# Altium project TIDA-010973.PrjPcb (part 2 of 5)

## Sheet TIDA-010973_SOM_PMIC.SchDoc
size 558 x 431 mm; Date: Not shown in title block; ApprovedBy: Not shown in title block; CheckedBy: Not shown in title block; Author: Not shown in title block; CompanyName: Not shown in title block; Engineer: Not shown in title block; Organization: Not shown in title block; Address1: Not shown in title block; Address2: Not shown in title block; Address3: Not shown in title block; Address4: Not shown in title block; DocumentNumber: 2; Revision: Use project parameter SCH_Rev; SheetNumber: 3; SheetTotal: 15; PageSetup: Record=PageOptions¦CenterHorizontal=True¦CenterVertical=True¦PrintScale=1.00¦XCorrection=1.00¦YCorrection=1.00¦PrintKind=0¦BorderSize=5000000¦LeftOffset=0¦BottomOffset=0¦Orientation=2¦PaperLength=1000¦PaperWidth=1000¦Scale=100¦PaperSource=15¦PrintQuality=600¦MediaType=1¦DitherType=10¦PaperKind=Letter¦PrintScaleMode=1
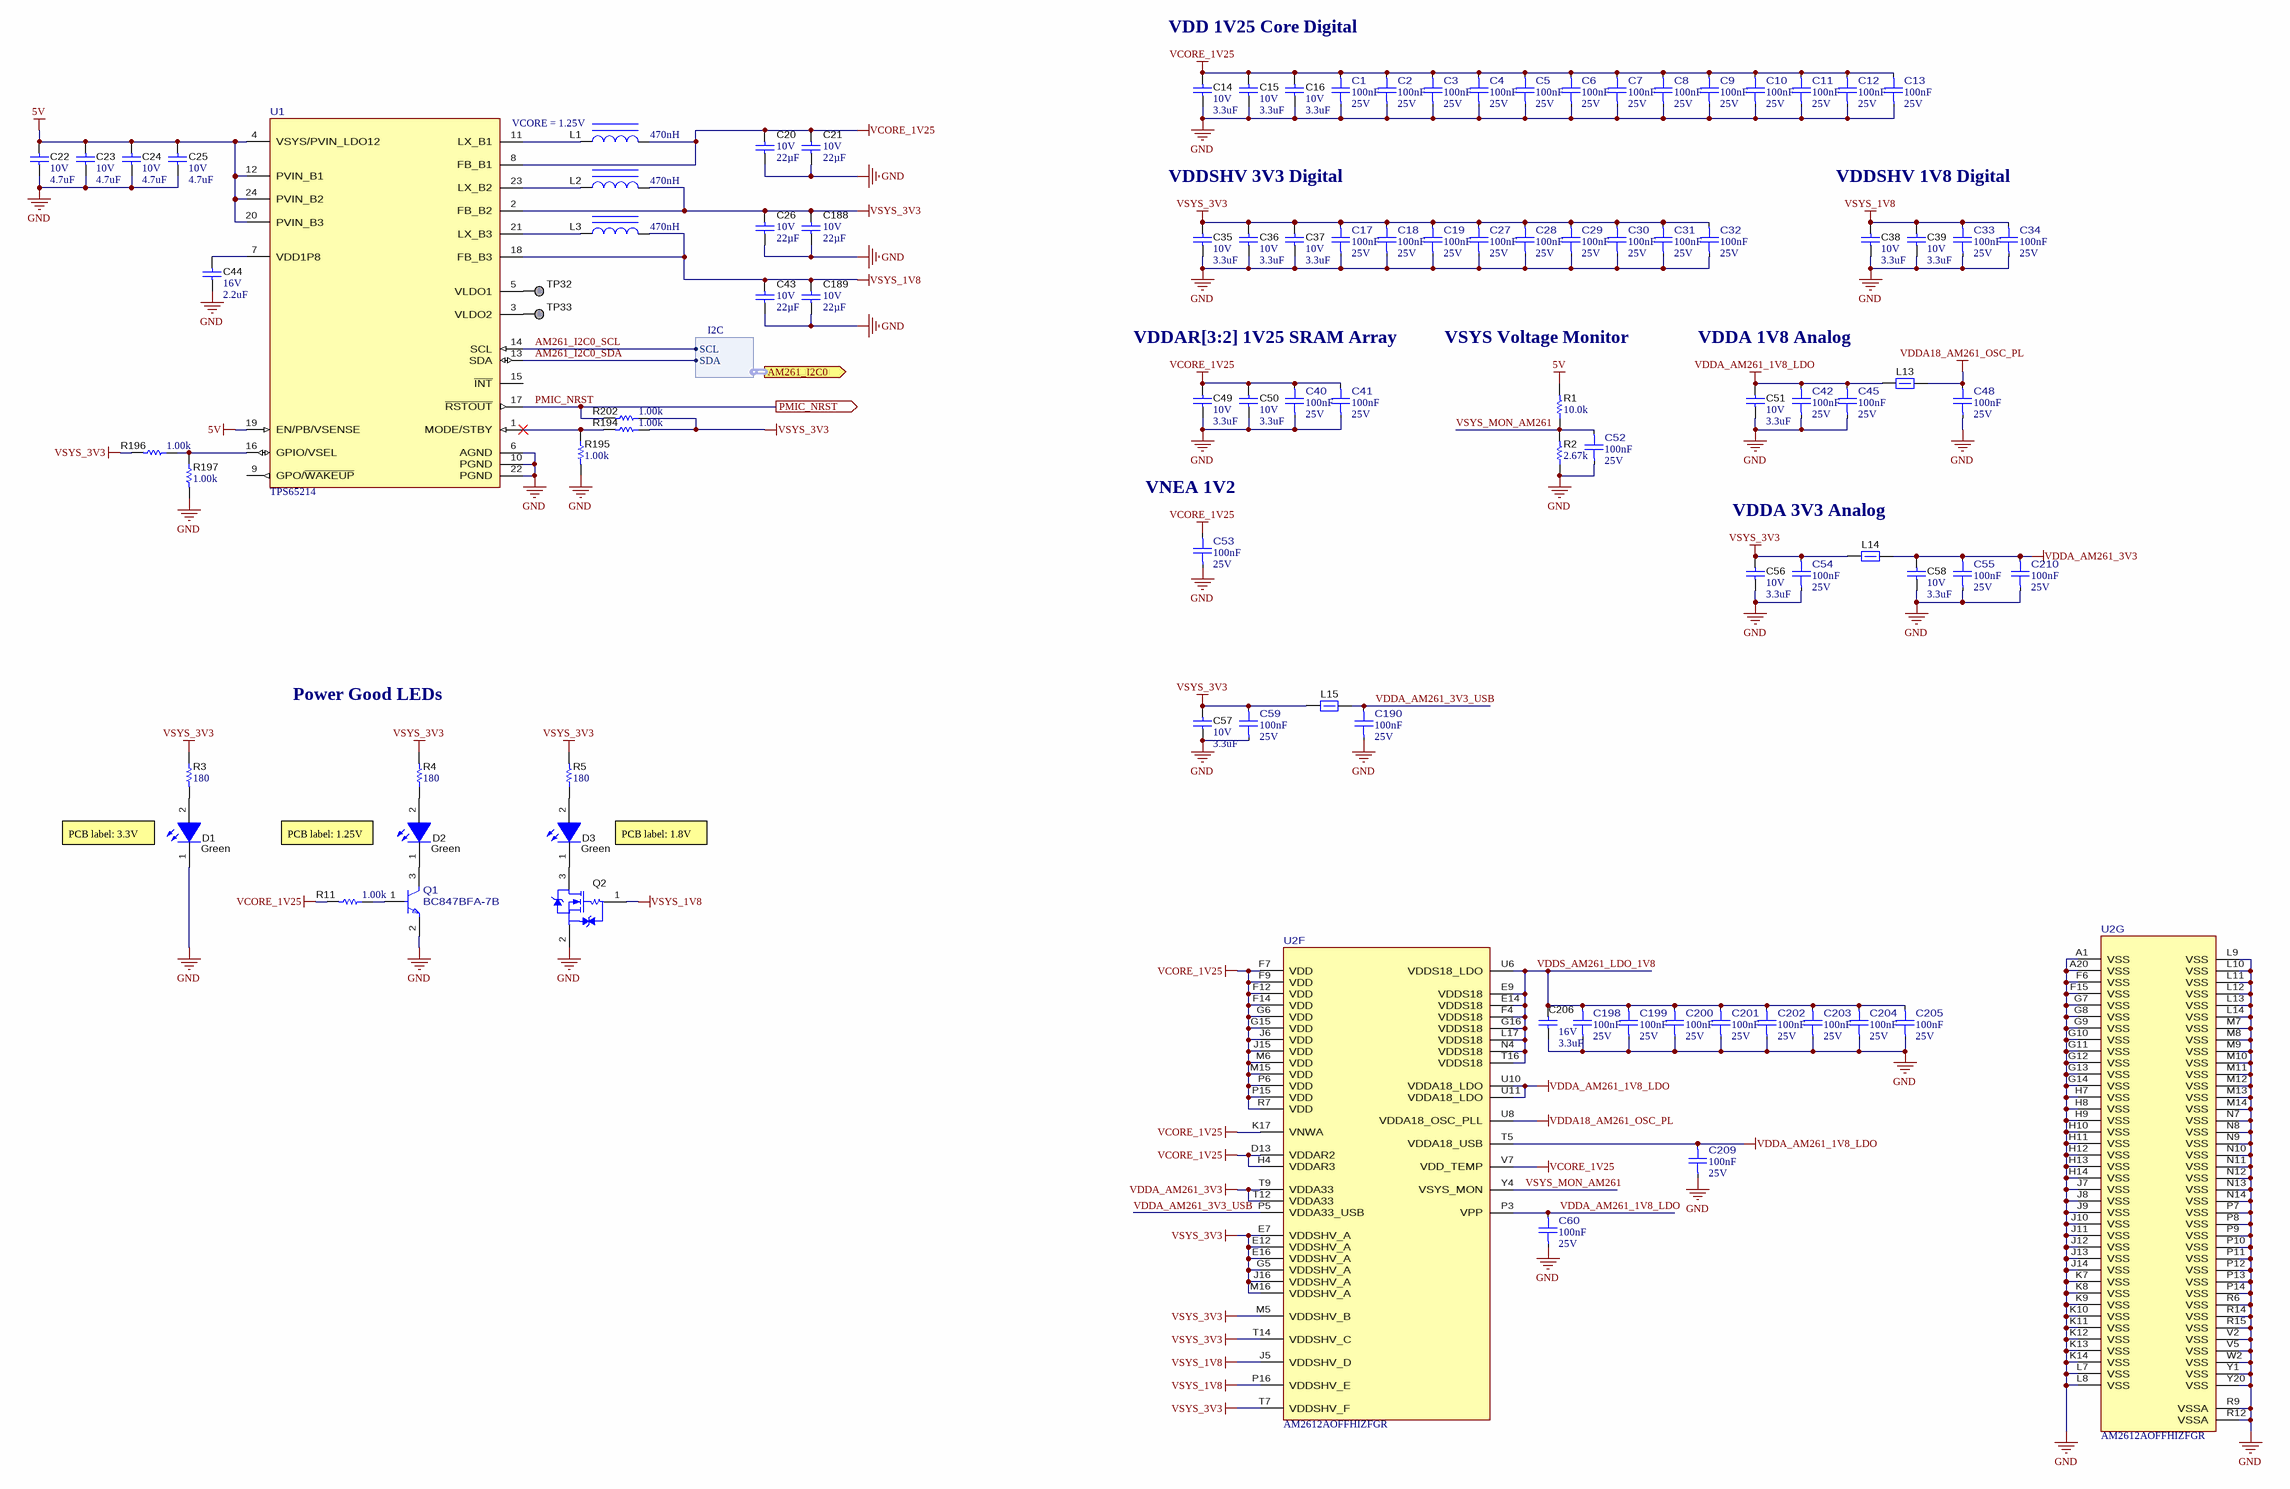
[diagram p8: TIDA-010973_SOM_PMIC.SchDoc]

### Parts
C1  ValueDisplayed: 100nF  VDC_V: 25V  [FP-885012104005_0201-IPC_C]  (hidden comment: 885012104005)
C2  ValueDisplayed: 100nF  VDC_V: 25V  [FP-885012104005_0201-IPC_C]  (hidden comment: 885012104005)
C3  ValueDisplayed: 100nF  VDC_V: 25V  [FP-885012104005_0201-IPC_C]  (hidden comment: 885012104005)
C4  ValueDisplayed: 100nF  VDC_V: 25V  [FP-885012104005_0201-IPC_C]  (hidden comment: 885012104005)
C5  ValueDisplayed: 100nF  VDC_V: 25V  [FP-885012104005_0201-IPC_C]  (hidden comment: 885012104005)
C6  ValueDisplayed: 100nF  VDC_V: 25V  [FP-885012104005_0201-IPC_C]  (hidden comment: 885012104005)
C7  ValueDisplayed: 100nF  VDC_V: 25V  [FP-885012104005_0201-IPC_C]  (hidden comment: 885012104005)
C8  ValueDisplayed: 100nF  VDC_V: 25V  [FP-885012104005_0201-IPC_C]  (hidden comment: 885012104005)
C9  ValueDisplayed: 100nF  VDC_V: 25V  [FP-885012104005_0201-IPC_C]  (hidden comment: 885012104005)
C10  ValueDisplayed: 100nF  VDC_V: 25V  [FP-885012104005_0201-IPC_C]  (hidden comment: 885012104005)
C11  ValueDisplayed: 100nF  VDC_V: 25V  [FP-885012104005_0201-IPC_C]  (hidden comment: 885012104005)
C12  ValueDisplayed: 100nF  VDC_V: 25V  [FP-885012104005_0201-IPC_C]  (hidden comment: 885012104005)
C13  ValueDisplayed: 100nF  VDC_V: 25V  [FP-885012104005_0201-IPC_C]  (hidden comment: 885012104005)
C14  VDC_V: 10V  ValueDisplayed: 3.3uF  [0402L]  (hidden comment: C1005X5R1A335K050BC)
C15  VDC_V: 10V  ValueDisplayed: 3.3uF  [0402L]  (hidden comment: C1005X5R1A335K050BC)
C16  VDC_V: 10V  ValueDisplayed: 3.3uF  [0402L]  (hidden comment: C1005X5R1A335K050BC)
C17  ValueDisplayed: 100nF  VDC_V: 25V  [FP-885012104005_0201-IPC_C]  (hidden comment: 885012104005)
C18  ValueDisplayed: 100nF  VDC_V: 25V  [FP-885012104005_0201-IPC_C]  (hidden comment: 885012104005)
C19  ValueDisplayed: 100nF  VDC_V: 25V  [FP-885012104005_0201-IPC_C]  (hidden comment: 885012104005)
C20  VDC_V: 10V  ValueDisplayed: 22µF  [0805_150]  (hidden comment: 885012107011)
C21  VDC_V: 10V  ValueDisplayed: 22µF  [0805_150]  (hidden comment: 885012107011)
C22  VDC_V: 10V  ValueDisplayed: 4.7uF  [0402_065S]  (hidden comment: C1005X5R1A475K050BC)
C23  VDC_V: 10V  ValueDisplayed: 4.7uF  [0402_065S]  (hidden comment: C1005X5R1A475K050BC)
C24  VDC_V: 10V  ValueDisplayed: 4.7uF  [0402_065S]  (hidden comment: C1005X5R1A475K050BC)
C25  VDC_V: 10V  ValueDisplayed: 4.7uF  [0402_065S]  (hidden comment: C1005X5R1A475K050BC)
C26  VDC_V: 10V  ValueDisplayed: 22µF  [0805_150]  (hidden comment: 885012107011)
C27  ValueDisplayed: 100nF  VDC_V: 25V  [FP-885012104005_0201-IPC_C]  (hidden comment: 885012104005)
C28  ValueDisplayed: 100nF  VDC_V: 25V  [FP-885012104005_0201-IPC_C]  (hidden comment: 885012104005)
C29  ValueDisplayed: 100nF  VDC_V: 25V  [FP-885012104005_0201-IPC_C]  (hidden comment: 885012104005)
C30  ValueDisplayed: 100nF  VDC_V: 25V  [FP-885012104005_0201-IPC_C]  (hidden comment: 885012104005)
C31  ValueDisplayed: 100nF  VDC_V: 25V  [FP-885012104005_0201-IPC_C]  (hidden comment: 885012104005)
C32  ValueDisplayed: 100nF  VDC_V: 25V  [FP-885012104005_0201-IPC_C]  (hidden comment: 885012104005)
C33  ValueDisplayed: 100nF  VDC_V: 25V  [FP-885012104005_0201-IPC_C]  (hidden comment: 885012104005)
C34  ValueDisplayed: 100nF  VDC_V: 25V  [FP-885012104005_0201-IPC_C]  (hidden comment: 885012104005)
C35  VDC_V: 10V  ValueDisplayed: 3.3uF  [0402L]  (hidden comment: C1005X5R1A335K050BC)
C36  VDC_V: 10V  ValueDisplayed: 3.3uF  [0402L]  (hidden comment: C1005X5R1A335K050BC)
C37  VDC_V: 10V  ValueDisplayed: 3.3uF  [0402L]  (hidden comment: C1005X5R1A335K050BC)
C38  VDC_V: 10V  ValueDisplayed: 3.3uF  [0402L]  (hidden comment: C1005X5R1A335K050BC)
C39  VDC_V: 10V  ValueDisplayed: 3.3uF  [0402L]  (hidden comment: C1005X5R1A335K050BC)
C40  ValueDisplayed: 100nF  VDC_V: 25V  [FP-885012104005_0201-MFG]  (hidden comment: 885012104005)
C41  ValueDisplayed: 100nF  VDC_V: 25V  [FP-885012104005_0201-MFG]  (hidden comment: 885012104005)
C42  ValueDisplayed: 100nF  VDC_V: 25V  [FP-885012104005_0201-IPC_C]  (hidden comment: 885012104005)
C43  VDC_V: 10V  ValueDisplayed: 22µF  [0805_150]  (hidden comment: 885012107011)
C44  VDC_V: 16V  ValueDisplayed: 2.2uF  [0603L]  (hidden comment: 885012106018)
C45  ValueDisplayed: 100nF  VDC_V: 25V  [FP-885012104005_0201-IPC_C]  (hidden comment: 885012104005)
C48  ValueDisplayed: 100nF  VDC_V: 25V  [FP-885012104005_0201-IPC_C]  (hidden comment: 885012104005)
C49  VDC_V: 10V  ValueDisplayed: 3.3uF  [0402L]  (hidden comment: C1005X5R1A335K050BC)
C50  VDC_V: 10V  ValueDisplayed: 3.3uF  [0402L]  (hidden comment: C1005X5R1A335K050BC)
C51  VDC_V: 10V  ValueDisplayed: 3.3uF  [0402L]  (hidden comment: C1005X5R1A335K050BC)
C52  ValueDisplayed: 100nF  VDC_V: 25V  [FP-885012104005_0201-IPC_C]  (hidden comment: 885012104005)
C53  ValueDisplayed: 100nF  VDC_V: 25V  [FP-885012104005_0201-IPC_C]  (hidden comment: 885012104005)
C54  ValueDisplayed: 100nF  VDC_V: 25V  [FP-885012104005_0201-IPC_C]  (hidden comment: 885012104005)
C55  ValueDisplayed: 100nF  VDC_V: 25V  [FP-885012104005_0201-IPC_C]  (hidden comment: 885012104005)
C56  VDC_V: 10V  ValueDisplayed: 3.3uF  [0402L]  (hidden comment: C1005X5R1A335K050BC)
C57  VDC_V: 10V  ValueDisplayed: 3.3uF  [0402L]  (hidden comment: C1005X5R1A335K050BC)
C58  VDC_V: 10V  ValueDisplayed: 3.3uF  [0402L]  (hidden comment: C1005X5R1A335K050BC)
C59  ValueDisplayed: 100nF  VDC_V: 25V  [FP-885012104005_0201-IPC_C]  (hidden comment: 885012104005)
C60  ValueDisplayed: 100nF  VDC_V: 25V  [FP-885012104005_0201-IPC_C]  (hidden comment: 885012104005)
C188  VDC_V: 10V  ValueDisplayed: 22µF  [0805_150]  (hidden comment: 885012107011)
C189  VDC_V: 10V  ValueDisplayed: 22µF  [0805_150]  (hidden comment: 885012107011)
C190  ValueDisplayed: 100nF  VDC_V: 25V  [FP-885012104005_0201-IPC_C]  (hidden comment: 885012104005)
C198  ValueDisplayed: 100nF  VDC_V: 25V  [FP-885012104005_0201-IPC_C]  (hidden comment: 885012104005)
C199  ValueDisplayed: 100nF  VDC_V: 25V  [FP-885012104005_0201-IPC_C]  (hidden comment: 885012104005)
C200  ValueDisplayed: 100nF  VDC_V: 25V  [FP-885012104005_0201-IPC_C]  (hidden comment: 885012104005)
C201  ValueDisplayed: 100nF  VDC_V: 25V  [FP-885012104005_0201-IPC_C]  (hidden comment: 885012104005)
C202  ValueDisplayed: 100nF  VDC_V: 25V  [FP-885012104005_0201-IPC_C]  (hidden comment: 885012104005)
C203  ValueDisplayed: 100nF  VDC_V: 25V  [FP-885012104005_0201-IPC_C]  (hidden comment: 885012104005)
C204  ValueDisplayed: 100nF  VDC_V: 25V  [FP-885012104005_0201-IPC_C]  (hidden comment: 885012104005)
C205  ValueDisplayed: 100nF  VDC_V: 25V  [FP-885012104005_0201-IPC_C]  (hidden comment: 885012104005)
C206  VDC_V: 16V  ValueDisplayed: 3.3uF  [0603L]  (hidden comment: C1608X6S1C335K080AC)
C209  ValueDisplayed: 100nF  VDC_V: 25V  [FP-885012104005_0201-IPC_C]  (hidden comment: 885012104005)
C210  ValueDisplayed: 100nF  VDC_V: 25V  [FP-885012104005_0201-IPC_C]  (hidden comment: 885012104005)
D1  value Green  [WL-SMCW_GREEN]  (hidden comment: 150060VS75000)
D2  value Green  [WL-SMCW_GREEN]  (hidden comment: 150060VS75000)
D3  value Green  [WL-SMCW_GREEN]  (hidden comment: 150060VS75000)
L1  ValueDisplayed: 470nH  [WE-PMCI_0603LP]  (hidden comment: 74479262147)
L2  ValueDisplayed: 470nH  [WE-PMCI_0603LP]  (hidden comment: 74479262147)
L3  ValueDisplayed: 470nH  [WE-PMCI_0603LP]  (hidden comment: 74479262147)
L13  74279271  [0402L]  (value not drawn)
L14  74279271  [0402L]  (value not drawn)
L15  74279271  [0402L]  (value not drawn)
Q1  BC847BFA-7B  [FP-BC847BFA-7B_DFN3-MFG]
Q2  CSD13383F4  [YJC0003A]  (value not drawn)
R1  ValueDisplayed: 10.0k  [0402L]  (hidden comment: CRCW040210K0FKED)
R2  ValueDisplayed: 2.67k  [0402L]  (hidden comment: CRCW04022K67FKED)
R3  ValueDisplayed: 180  [0402L]  (hidden comment: CRCW0402180RJNED)
R4  ValueDisplayed: 180  [0402L]  (hidden comment: CRCW0402180RJNED)
R5  ValueDisplayed: 180  [0402L]  (hidden comment: CRCW0402180RJNED)
R11  ValueDisplayed: 1.00k  [0402L]  (hidden comment: CRCW04021K00FKED)
R194  ValueDisplayed: 1.00k  [0402L]  (hidden comment: CRCW04021K00FKED)
R195  ValueDisplayed: 1.00k  [0402L]  (hidden comment: CRCW04021K00FKED)
R196  ValueDisplayed: 1.00k  [0402L]  (hidden comment: CRCW04021K00FKED)
R197  ValueDisplayed: 1.00k  [0402L]  (hidden comment: CRCW04021K00FKED)
R202  ValueDisplayed: 1.00k  [0402L]  (hidden comment: CRCW04021K00FKED)
TP32  TESTPOINT  [TP_25MIL-SMT]  (value not drawn)  (no BOM)
TP33  TESTPOINT  [TP_25MIL-SMT]  (value not drawn)  (no BOM)
U1  TPS65214  [VAF0024A-MFG]
U2  AM2612AOFFHIZFGR  [ZFG0304A-MFG]  (parts F,G of 7)

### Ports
AM261_I2C0 (out, harness I2C), PMIC_NRST (out)

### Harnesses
I2C: SCL, SDA

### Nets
5V: C22.1 C23.1 C24.1 C25.1 R1.2 U1.4(VSYS/PVIN_LDO12) U1.12(PVIN_B1) U1.19(EN/PB/VSENSE) U1.20(PVIN_B3) U1.24(PVIN_B2)
GND: C1.1 C2.1 C3.1 C4.1 C5.1 C6.1 C7.1 C8.1 C9.1 C10.1 C11.1 C12.1 C13.1 C14.2 C15.2 C16.2 C17.1 C18.1 C19.1 C20.2 C21.2 C22.2 C23.2 C24.2 C25.2 C26.2 C27.1 C28.1 C29.1 C30.1 C31.1 C32.1 C33.1 C34.1 C35.2 C36.2 C37.2 C38.2 C39.2 C40.1 C41.1 C42.1 C43.2 C44.2 C45.1 C48.1 C49.2 C50.2 C51.2 C52.1 C53.1 C54.1 C55.1 C56.2 C57.2 C58.2 C59.1 C60.1 C188.2 C189.2 C190.1 C198.1 C199.1 C200.1 C201.1 C202.1 C203.1 C204.1 C205.1 C206.2 C209.2 C210.1 D1.1(K) Q1.2(E) Q2.2(S) R2.1 R195.2 R197.2 U1.6(AGND) U1.10(PGND) U1.22(PGND) U2.A1(VSS) U2.A20(VSS) U2.F6(VSS) U2.F15(VSS) U2.G7(VSS) U2.G8(VSS) U2.G9(VSS) U2.G10(VSS) U2.G11(VSS) U2.G12(VSS) U2.G13(VSS) U2.G14(VSS) U2.H7(VSS) U2.H8(VSS) U2.H9(VSS) U2.H10(VSS) U2.H11(VSS) U2.H12(VSS) U2.H13(VSS) U2.H14(VSS) U2.J7(VSS) U2.J8(VSS) U2.J9(VSS) U2.J10(VSS) U2.J11(VSS) U2.J12(VSS) U2.J13(VSS) U2.J14(VSS) U2.K7(VSS) U2.K8(VSS) U2.K9(VSS) U2.K10(VSS) U2.K11(VSS) U2.K12(VSS) U2.K13(VSS) U2.K14(VSS) U2.L7(VSS) U2.L8(VSS) U2.L9(VSS) U2.L10(VSS) U2.L11(VSS) U2.L12(VSS) U2.L13(VSS) U2.L14(VSS) U2.M7(VSS) U2.M8(VSS) U2.M9(VSS) U2.M10(VSS) U2.M11(VSS) U2.M12(VSS) U2.M13(VSS) U2.M14(VSS) U2.N7(VSS) U2.N8(VSS) U2.N9(VSS) U2.N10(VSS) U2.N11(VSS) U2.N12(VSS) U2.N13(VSS) U2.N14(VSS) U2.P7(VSS) U2.P8(VSS) U2.P9(VSS) U2.P10(VSS) U2.P11(VSS) U2.P12(VSS) U2.P13(VSS) U2.P14(VSS) U2.R6(VSS) U2.R9(VSSA) U2.R12(VSSA) U2.R14(VSS) U2.R15(VSS) U2.V2(VSS) U2.V5(VSS) U2.W2(VSS) U2.Y1(VSS) U2.Y20(VSS)
VCORE_1V25: C1.2 C2.2 C3.2 C4.2 C5.2 C6.2 C7.2 C8.2 C9.2 C10.2 C11.2 C12.2 C13.2 C14.1 C15.1 C16.1 C20.1 C21.1 C40.2 C41.2 C49.1 C50.1 C53.2 L1.2 R11.2 U1.8(FB_B1) U2.D13(VDDAR2) U2.F7(VDD) U2.F9(VDD) U2.F12(VDD) U2.F14(VDD) U2.G6(VDD) U2.G15(VDD) U2.H4(VDDAR3) U2.J6(VDD) U2.J15(VDD) U2.K17(VNWA) U2.M6(VDD) U2.M15(VDD) U2.P6(VDD) U2.P15(VDD) U2.R7(VDD) U2.V7(VDD_TEMP)
VDDA18_AM261_OSC_PL: C48.2 L13.2 U2.U8(VDDA18_OSC_PLL)
VDDA_AM261_1V8_LDO: C42.2 C45.2 C51.1 C60.2 C209.1 L13.1 U2.P3(VPP) U2.T5(VDDA18_USB) U2.U10(VDDA18_LDO) U2.U11(VDDA18_LDO)
VDDA_AM261_3V3: C55.2 C58.1 C210.2 L14.2 U2.T9(VDDA33) U2.T12(VDDA33)
VSYS_1V8: C33.2 C34.2 C38.1 C39.1 C43.1 C189.1 L3.2 Q2.1(G) U1.18(FB_B3) U2.J5(VDDSHV_D) U2.P16(VDDSHV_E)
VSYS_3V3: C17.2 C18.2 C19.2 C26.1 C27.2 C28.2 C29.2 C30.2 C31.2 C32.2 C35.1 C36.1 C37.1 C54.2 C56.1 C57.1 C59.2 C188.1 L2.2 L14.1 L15.1 R3.1 R4.2 R5.2 R194.1 R196.2 R202.1 U1.2(FB_B2) U2.E7(VDDSHV_A) U2.E12(VDDSHV_A) U2.E16(VDDSHV_A) U2.G5(VDDSHV_A) U2.J16(VDDSHV_A) U2.M5(VDDSHV_B) U2.M16(VDDSHV_A) U2.T7(VDDSHV_F) U2.T14(VDDSHV_C)
AM261_I2C0_SCL: U1.14(SCL) ; port AM261_I2C0.SCL  [project net AM261_I2C0.SCL]
AM261_I2C0_SDA: U1.13(SDA) ; port AM261_I2C0.SDA  [project net AM261_I2C0.SDA]
PMIC_NRST: R202.2 U1.17(~{RSTOUT}) ; port PMIC_NRST
VDDA_AM261_3V3_USB: C190.2 L15.2 U2.P5(VDDA33_USB)
VDDS_AM261_LDO_1V8: C198.2 C199.2 C200.2 C201.2 C202.2 C203.2 C204.2 C205.2 C206.1 U2.E9(VDDS18) U2.E14(VDDS18) U2.F4(VDDS18) U2.G16(VDDS18) U2.L17(VDDS18) U2.N4(VDDS18) U2.T16(VDDS18) U2.U6(VDDS18_LDO)
VSYS_MON_AM261: C52.2 R1.1 R2.2 U2.Y4(VSYS_MON)
NetC44_1: C44.1 U1.7(VDD1P8)
NetD1_2: D1.2(A) R3.2
NetD2_1: D2.1(K) Q1.3(C)
NetD2_2: D2.2(A) R4.1
NetD3_1: D3.1(K) Q2.3(D)
NetD3_2: D3.2(A) R5.1
NetL1_1: L1.1 U1.11(LX_B1)
NetL2_1: L2.1 U1.23(LX_B2)
NetL3_1: L3.1 U1.21(LX_B3)
NetQ1_1: Q1.1(B) R11.1
NetR194_2: R194.2 R195.1 U1.1(MODE/STBY)
NetR196_1: R196.1 R197.1 U1.16(GPIO/VSEL)
NetTP32_1: TP32.1 U1.5(VLDO1)
NetTP33_1: TP33.1 U1.3(VLDO2)

Not connected (* = marked no-connect by the designer): U1 9(GPO/~{WAKEUP}) 15(~{INT})

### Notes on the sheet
- VDD 1V25 Core Digital
- VCORE = 1.25V
- VDDSHV 3V3 Digital
- VDDSHV 1V8 Digital
- VDDAR[3:2] 1V25 SRAM Array
- VSYS Voltage Monitor
- VDDA 1V8 Analog
- (near C53) VNEA 1V2
- VDDA 3V3 Analog
- Power Good LEDs
- PCB label: 3.3V
- PCB label: 1.25V
- PCB label: 1.8V

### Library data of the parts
C1-C13 C17-C19 C27-C34 C40-C42 C45 C48 C52-C55 C59 C60 C190 C198-C205 C209 C210 = CMP-0049180-1: 0.1 µF ±10% 25V Ceramic Capacitor X5R 0201 (0603 Metric); Manufacturer: Wurth Electronics; AEC Qualified: No; SizeZ_mm: 0.33mm; TempCo: 15%; Value: 100nF
C14-C16 C35-C39 C49-C51 C56-C58 = CMP-0006265-2: CAP, CERM, 3.3 uF, 10 V, +/- 10%, X5R, 0402; Manufacturer: TDK; TaMin_C: -55°C; ESR_ohm: 4.157m; Polarized: N; SizeAreaWB_mm2: 3; Value1: 0.004157 ohm; U/M: EA; Value: 3.3uF; TaMax_C: 85°C; SizeZ_mm: 0.6; SizeX_mm: 1; SizeY_mm: 0.5; Cap_Case: 0402; Cap_F: 3.3µF; IRMS_A: 2.45391A; AEC Category: Q200
C20 C21 C26 C43 C188 C189 = CMP-0078153-1: CAP, CERM, 22 µF, 10 V,+/- 20%, X5R, 0805; Manufacturer: Wurth Elektronik; TaMin_C: -55°C; Polarized: N; SizeAreaWB_mm2: 6.75; U/M: EA; Value: 22uF; TaMax_C: 85°C; SizeZ_mm: 1.5; SizeX_mm: 2; SizeY_mm: 1.25; Cap_Case: 0805; SizeArea_mm2: 2.5; AEC Category: Q200
C22-C25 = CMP-0006268-2: CAP, CERM, 4.7 uF, 10 V, +/- 10%, X5R, 0402; Manufacturer: TDK; TaMin_C: -55°C; ESR_ohm: 3.417m; Polarized: N; SizeAreaWB_mm2: 3; Value1: 0.003417 ohm; U/M: EA; Value: 4.7uF; TaMax_C: 85°C; SizeZ_mm: 0.65; SizeX_mm: 1; SizeY_mm: 0.5; Cap_Case: 0402_065; Cap_F: 4.7µF; IRMS_A: 2.7063A; AEC Category: Q200
C44 = CMP-0006825-5: CAP, CERM, 2.2 uF, 16 V, +/- 20%, X5R, 0603; Manufacturer: Wurth Elektronik; TaMin_C: -55°C; Polarized: N; SizeAreaWB_mm2: 4.68; Value1: Unknown; U/M: EA; Value: 2.2uF; TaMax_C: 85°C; SizeZ_mm: 1; SizeX_mm: 1.6; SizeY_mm: 0.8; Cap_Case: 0603; SizeArea_mm2: 1.28; Cap_F: 2.2µF; AEC Category: Q200
C206 = CMP-0007027-4: CAP, CERM, 3.3 uF, 16 V, +/- 10%, X6S, 0603; Manufacturer: TDK; TaMin_C: -55°C; ESR_ohm: 4.796m; Polarized: N; SizeAreaWB_mm2: 4.68; Value1: 0.004796 ohm; U/M: EA; Value: 3.3uF; TaMax_C: 105°C; SizeZ_mm: 1; SizeX_mm: 1.6; SizeY_mm: 0.8; Cap_Case: 0603; SizeArea_mm2: 1.28; Cap_F: 3.3µF; IRMS_A: 2.37519A; AEC Category: Q200
D1-D3 = CMP-0002894-2: LED, Green, SMD; Manufacturer: Wurth Elektronik; Type: AlInGaP; Value2: 2V; Io_A: 20mA; Value1: W
L1-L3 = CMP-0064306-1: Inductor, Shielded, 470 nH, 1.5 A, 0.1 ohm, SMD; Manufacturer: Wurth Elektronik; Isat: 2.5A @ 30% inductance drop; Irms: 1.5A @ 40C rise; Green_Lifecycle: Active; SizeAreaWB_mm2: 4.68; DCR_ohm: 1d; Green_REACh: Passed; Value1: 0.1 ohm; Value: 470nH; Imax_A: 1.5A; SizeZ_mm: 0.8; SizeX_mm: 1.6; SizeArea_mm2: 1.28; AEC Qualified: N; AEC Category: Q200
L13-L15 = CMP-0003214-1: Ferrite Bead, 120 ohm @ 100 MHz, 0.5 A, 0402; Manufacturer: Wurth Elektronik; Ztyp@1GHz_Ohm: 175.42; ZTyp@100MHz_Ohm: 120; SizeAreaWB_mm2: 3; DCR_ohm: 2d; Value1: 0.2 ohm; Value: 120 ohm; Imax_A: 5dA; SizeZ_mm: 0.6; SizeX_mm: 1; SizeY_mm: 0.5; Value2: 0.5A
Q1 = CMP-0090098-1: 100mA 45V NPN Signal Transistor DFN0806; Manufacturer: Diodes Inc.; Unity Gain Freq: 170MHz; Collector Base Voltage: 50V; Power_W: 435mW; AEC Qualified: Yes; Hfe Testic: 2mA; Number Of Npn: 1; Hfe Testvce: 5V; TJmax_C: +150°C; HfeMax: 470; Vceo_V: 150V; SizeZ_mm: 0.4mm; Emitter Base Voltage: 6V; Vcesat1_V: 122mV; Standoff Height: 0mm; Hfe Min: 200; AEC Grade: Grade 0; Rthja Max: 287°C/W
Q2 = CMP-0000198-1: MOSFET, N-CH, 12 V, 2.9 A, YJC0003A (PICOSTAR-3); Alternate Manufacturer: None; Manufacturer: Texas Instruments; SizeZ_mm: 0.35; ChType: N; Value2: 2 nC; Value1: 0.04; VdsMax_V: 12V; SizeX_mm: 1.035; SizeY_mm: 0.635; Vgs_V: 10V; Value: 12V; Rdson45_ohm: 0.044; SizeArea_mm2: 0.657225; AEC Category: Q101; IdsMax_A: 2.9A; SizeAreaWB_mm2: 3.327225; U/M: EA; QgTyp_nC: 2
R1 = CMP-0025958-3: RES, 10.0 k, 1%, 0.063 W, AEC-Q200 Grade 0, 0402; Manufacturer: Vishay-Dale; Power_W: 63mW; TempCo: 100 ppm/C; Value_Code: 10k0; Value: 10.0k; EIA_Code: E96; Res_ohm: 10k; SizeX_mm: 1; SizeY_mm: 0.5; SizeZ_mm: 0.6; Value2: 0.063W; AEC Qualified: Y; VDC_V: 50V; AEC Category: Q200; AEC Grade: 0
R2 = CMP-0026240-2: RES, 2.67 k, 1%, 0.063 W, AEC-Q200 Grade 0, 0402; Manufacturer: Vishay-Dale; Power_W: 63mW; TempCo: 100 ppm/C; Value_Code: 2k67; Value: 2.67k; EIA_Code: E96; SizeX_mm: 1; SizeY_mm: 0.5; SizeZ_mm: 0.6; Value2: 0.063W; AEC Qualified: Y; VDC_V: 50V; AEC Category: Q200; AEC Grade: 0
R3-R5 = CMP-0026849-3: RES, 180, 5%, 0.063 W, AEC-Q200 Grade 0, 0402; Manufacturer: Vishay-Dale; Power_W: 63mW; TempCo: 200 ppm/C; Value_Code: 180R; Value: 180; EIA_Code: E24; SizeX_mm: 1; SizeY_mm: 0.5; SizeZ_mm: 0.6; Value2: 0.063W; AEC Qualified: Y; VDC_V: 50V; AEC Category: Q200; AEC Grade: 0
R11 R194-R197 R202 = CMP-0026071-3: RES, 1.00 k, 1%, 0.063 W, AEC-Q200 Grade 0, 0402; Manufacturer: Vishay-Dale; Power_W: 63mW; TempCo: 100 ppm/C; Value_Code: 1k00; Value: 1.00k; EIA_Code: E96; Res_ohm: 1k; SizeX_mm: 1; SizeY_mm: 0.5; SizeZ_mm: 0.6; Value2: 0.063W; AEC Qualified: Y; VDC_V: 50V; AEC Category: Q200; AEC Grade: 0
TP32 TP33 = CMP-0078143-4: TEST POINT.  No entry in BOM.
U1 = CMP-0121651-1: Integrated Power Management IC for ARM Cortex®—Low Power Processors and FPGAs; Manufacturer: Texas Instruments; SizeZ_mm: 0.8mm; AEC Qualified: No; Max Supply Voltage: 5.5V; Min Supply Voltage: 2.5V; Number Of Outputs: 5; Output Voltage: 0.6-3.4/0.6-3.4/0.6-3.3/0.6-3.3V; Standoff Height: 0mm; TaMax_C: +105°C; TaMin_C: -40°C; TJmax_C: +125°C
U2 = CMP-0126016-1: ARM® Cortex®-R5F Sitara™ Microcontroller IC 32-Bit Dual-Core 500MHz 512KB (512K x 8) Tightly Coupled Memory (TCM) 304-NFBGA (13.25x13.25); Manufacturer: Texas Instruments; SizeZ_mm: 1.3mm; AEC Qualified: No; Core Architecture: ARM Cortex-R5F; Data Bus Width: 32bits; Interface: I2C,SPI,UART,CAN,USB,LIN,Ethernet; Max Supply Voltage: 3.465V; Min Supply Voltage: 1.14V; Number Of A/D Converters: 3; Number Of Adc Channels: 7; Number Of Cores: 2; Number Of Ethernet Channels: 1; Number Of I/Os: 141; Number Of Pwm Channels: 10; Number Of Spi Channels: 4; Number Of Uart Channels: 6; Ram Size: 1.5MBytes; Standoff Height: 0.23mm; TJmax_C: +125°C

## Sheet TIDA-010973_SOM_MCU.SchDoc
size 558 x 431 mm; Date: Not shown in title block; ApprovedBy: Not shown in title block; CheckedBy: Not shown in title block; Author: Not shown in title block; CompanyName: Not shown in title block; Engineer: Not shown in title block; Organization: Not shown in title block; Address1: Not shown in title block; Address2: Not shown in title block; Address3: Not shown in title block; Address4: Not shown in title block; DocumentNumber: 2; Revision: Use project parameter SCH_Rev; SheetNumber: 4; SheetTotal: 15; PageSetup: Record=PageOptions¦CenterHorizontal=True¦CenterVertical=True¦PrintScale=1.00¦XCorrection=1.00¦YCorrection=1.00¦PrintKind=0¦BorderSize=5000000¦LeftOffset=0¦BottomOffset=0¦Orientation=2¦PaperLength=1000¦PaperWidth=1000¦Scale=100¦PaperSource=15¦PrintQuality=600¦MediaType=1¦DitherType=10¦PaperKind=Letter¦PrintScaleMode=1
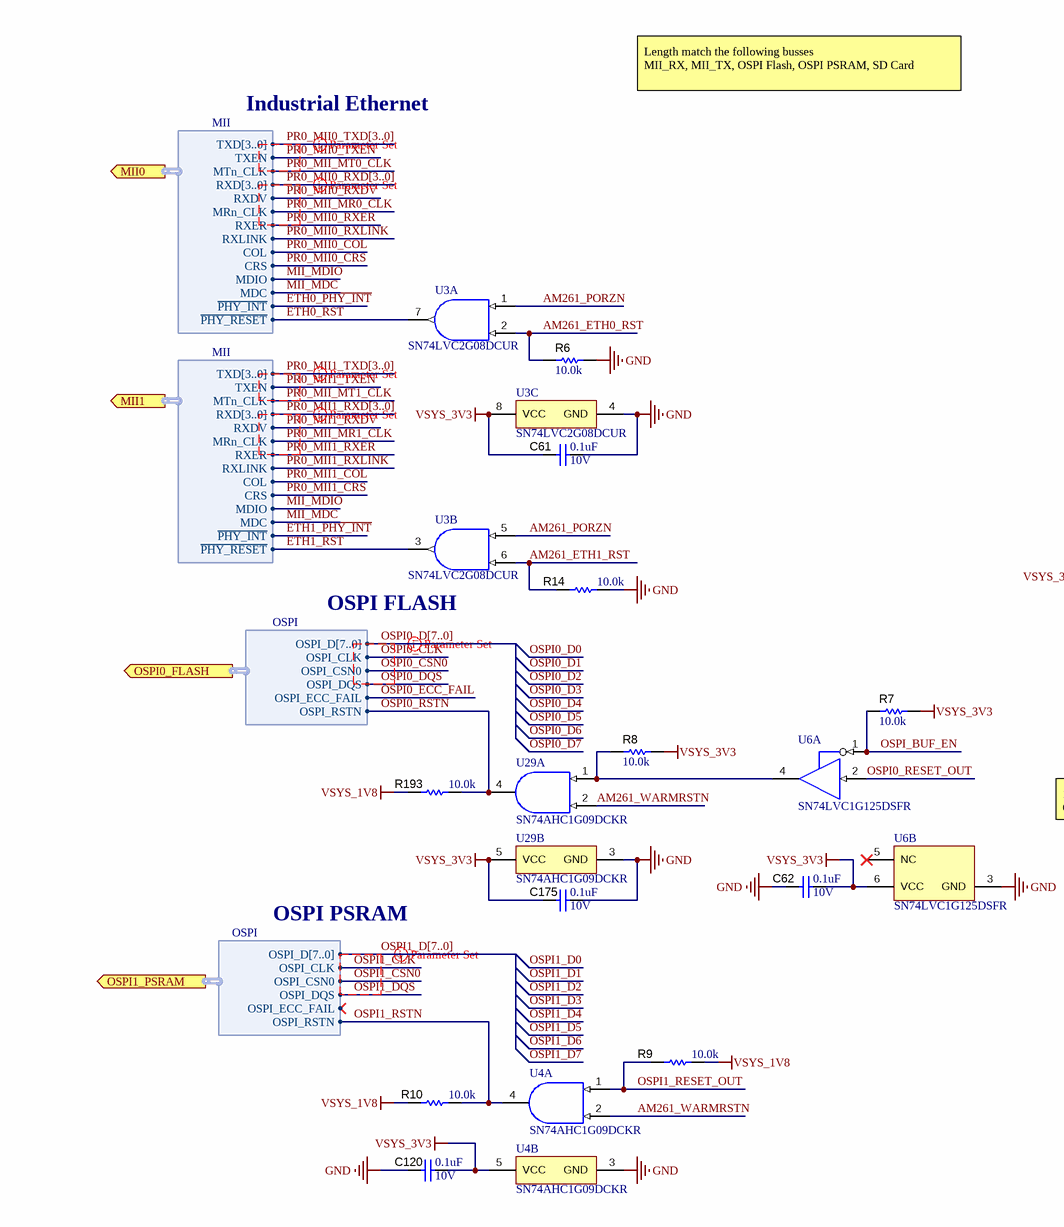
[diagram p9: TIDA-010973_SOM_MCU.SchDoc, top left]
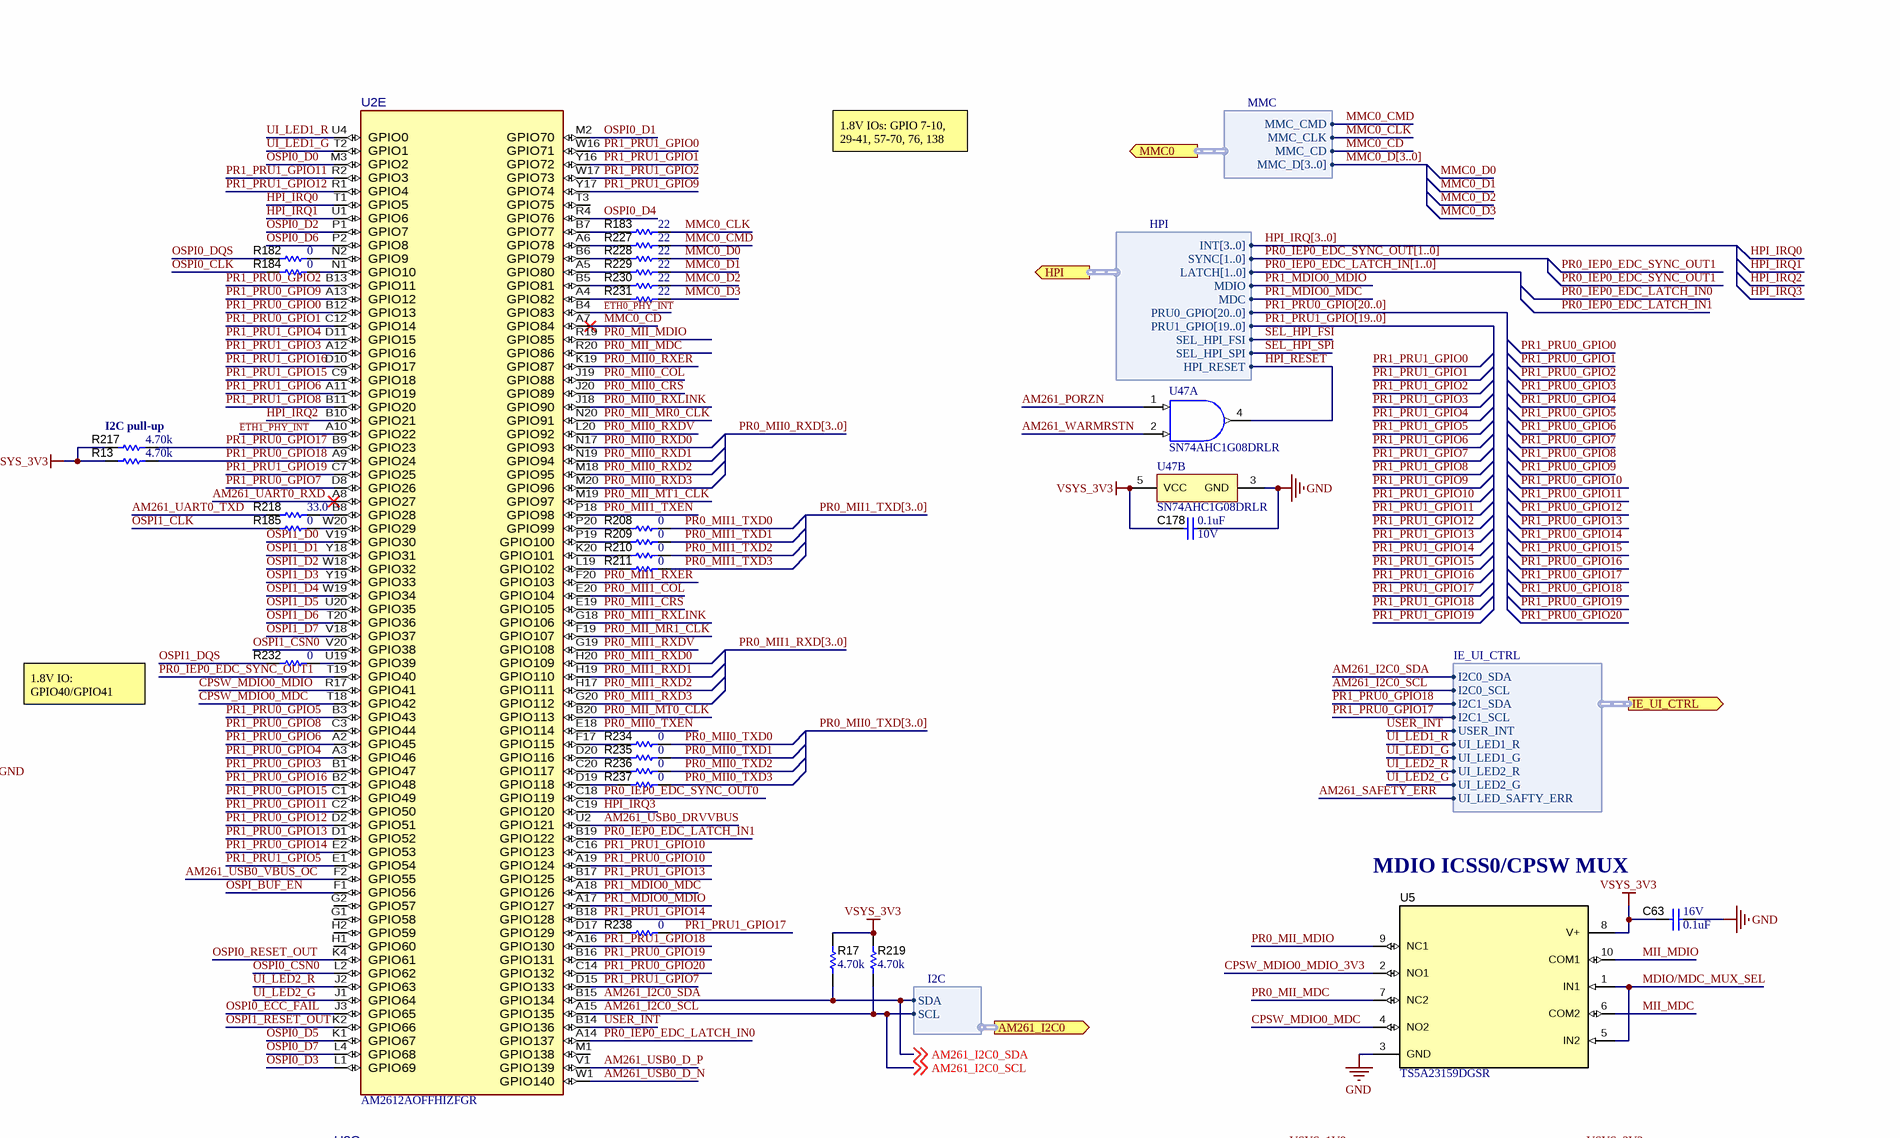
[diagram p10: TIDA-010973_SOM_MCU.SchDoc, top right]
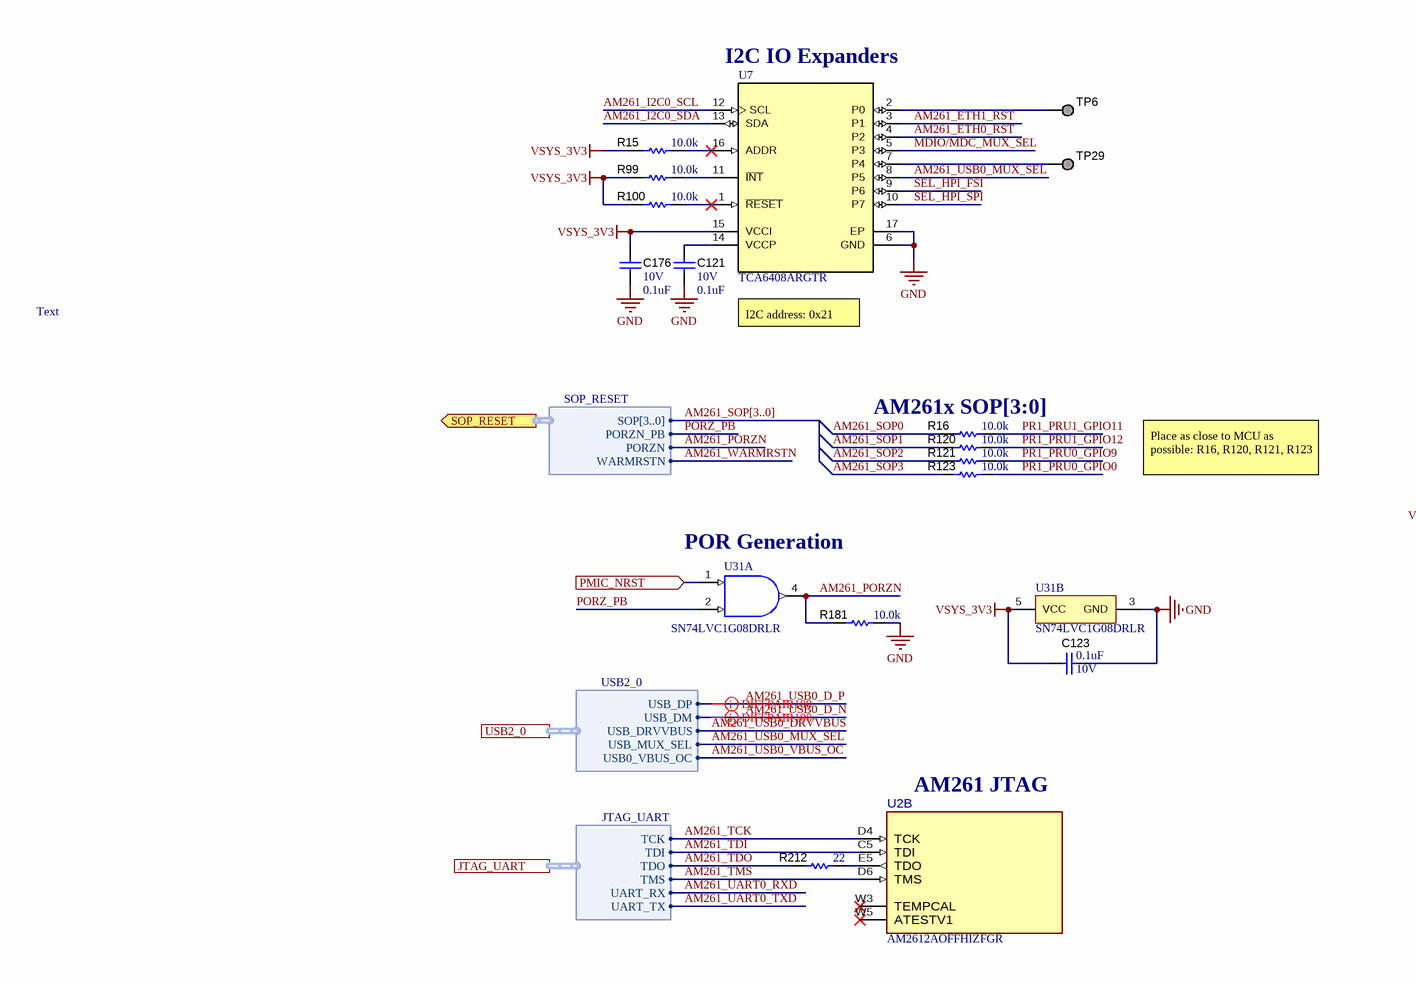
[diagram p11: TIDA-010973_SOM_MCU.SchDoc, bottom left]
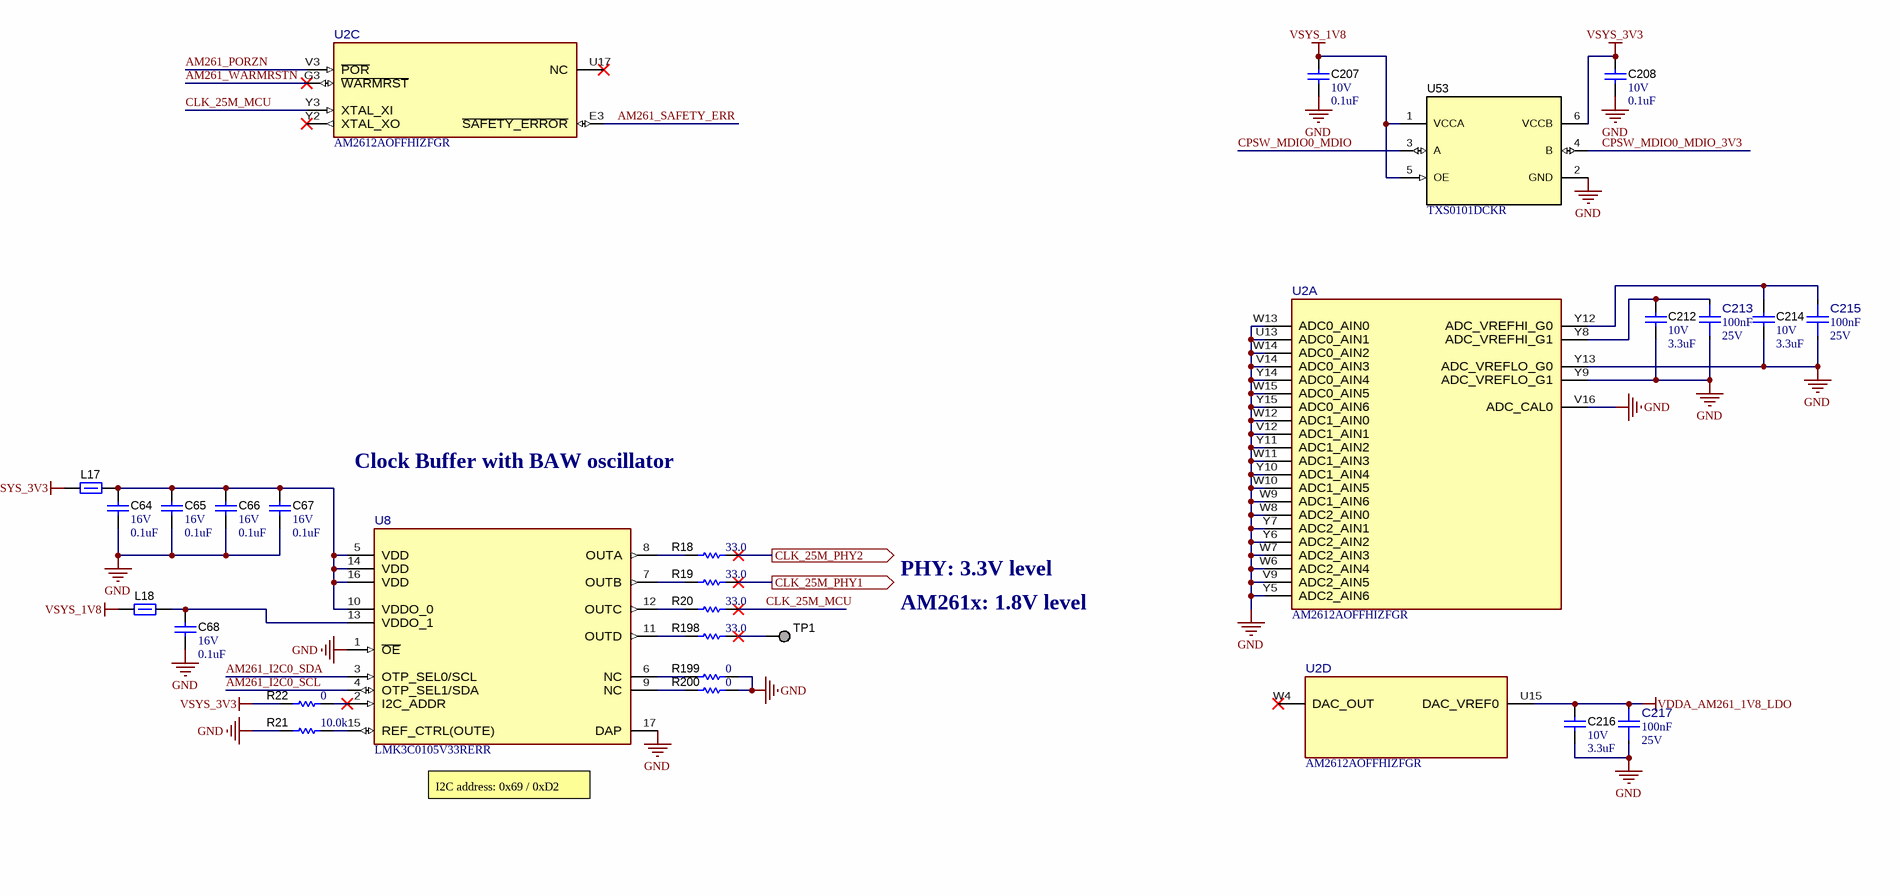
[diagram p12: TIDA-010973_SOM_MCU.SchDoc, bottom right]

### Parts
C61  VDC_V: 10V  ValueDisplayed: 0.1uF  [0402L]  (hidden comment: 885012105010)
C62  VDC_V: 10V  ValueDisplayed: 0.1uF  [0402L]  (hidden comment: 885012105010)
C63  VDC_V: 16V  ValueDisplayed: 0.1uF  [0402L]  (hidden comment: 885012205037)
C64  VDC_V: 16V  ValueDisplayed: 0.1uF  [0402L]  (hidden comment: 885012205037)
C65  VDC_V: 16V  ValueDisplayed: 0.1uF  [0402L]  (hidden comment: 885012205037)
C66  VDC_V: 16V  ValueDisplayed: 0.1uF  [0402L]  (hidden comment: 885012205037)
C67  VDC_V: 16V  ValueDisplayed: 0.1uF  [0402L]  (hidden comment: 885012205037)
C68  VDC_V: 16V  ValueDisplayed: 0.1uF  [0402L]  (hidden comment: 885012205037)
C120  VDC_V: 10V  ValueDisplayed: 0.1uF  [0402L]  (hidden comment: 885012105010)
C121  VDC_V: 10V  ValueDisplayed: 0.1uF  [0402L]  (hidden comment: 885012105010)
C123  VDC_V: 10V  ValueDisplayed: 0.1uF  [0402L]  (hidden comment: 885012105010)
C175  VDC_V: 10V  ValueDisplayed: 0.1uF  [0402L]  (hidden comment: 885012105010)
C176  VDC_V: 10V  ValueDisplayed: 0.1uF  [0402L]  (hidden comment: 885012105010)
C178  VDC_V: 10V  ValueDisplayed: 0.1uF  [0402L]  (hidden comment: 885012105010)
C207  VDC_V: 10V  ValueDisplayed: 0.1uF  [0402L]  (hidden comment: 885012105010)
C208  VDC_V: 10V  ValueDisplayed: 0.1uF  [0402L]  (hidden comment: 885012105010)
C212  VDC_V: 10V  ValueDisplayed: 3.3uF  [0402L]  (hidden comment: C1005X5R1A335K050BC)
C213  ValueDisplayed: 100nF  VDC_V: 25V  [FP-885012104005_0201-IPC_C]  (hidden comment: 885012104005)
C214  VDC_V: 10V  ValueDisplayed: 3.3uF  [0402L]  (hidden comment: C1005X5R1A335K050BC)
C215  ValueDisplayed: 100nF  VDC_V: 25V  [FP-885012104005_0201-IPC_C]  (hidden comment: 885012104005)
C216  VDC_V: 10V  ValueDisplayed: 3.3uF  [0402L]  (hidden comment: C1005X5R1A335K050BC)
C217  ValueDisplayed: 100nF  VDC_V: 25V  [FP-885012104005_0201-IPC_C]  (hidden comment: 885012104005)
L17  742792604  [0603L]  (value not drawn)
L18  742792604  [0603L]  (value not drawn)
R6  ValueDisplayed: 10.0k  [0402L]  (hidden comment: CRCW040210K0FKED)
R7  ValueDisplayed: 10.0k  [0402L]  (hidden comment: CRCW040210K0FKED)
R8  ValueDisplayed: 10.0k  [0402L]  (hidden comment: CRCW040210K0FKED)
R9  ValueDisplayed: 10.0k  [0402L]  (hidden comment: CRCW040210K0FKED)
R10  ValueDisplayed: 10.0k  [0402L]  (hidden comment: CRCW040210K0FKED)
R13  ValueDisplayed: 4.70k  [0201L]  (hidden comment: RC0201FR-074K7L)
R14  ValueDisplayed: 10.0k  [0402L]  (hidden comment: CRCW040210K0FKED)
R15  ValueDisplayed: 10.0k  [0402L]  (hidden comment: CRCW040210K0FKED)
R16  ValueDisplayed: 10.0k  [0201L]  (hidden comment: CRCW020110K0FKED)
R17  ValueDisplayed: 4.70k  [0201L]  (hidden comment: RC0201FR-074K7L)
R18  ValueDisplayed: 33.0  [0402L]  (hidden comment: RMCF0402FT33R0)
R19  ValueDisplayed: 33.0  [0402L]  (hidden comment: RMCF0402FT33R0)
R20  ValueDisplayed: 33.0  [0402L]  (hidden comment: RMCF0402FT33R0)
R21  ValueDisplayed: 10.0k  [0402L]  (hidden comment: CRCW040210K0FKED)
R22  ValueDisplayed: 0  [0402L]  (hidden comment: CRCW04020000Z0ED)
R99  ValueDisplayed: 10.0k  [0402L]  (hidden comment: CRCW040210K0FKED)
R100  ValueDisplayed: 10.0k  [0402L]  (hidden comment: CRCW040210K0FKED)
R120  ValueDisplayed: 10.0k  [0201L]  (hidden comment: CRCW020110K0FKED)
R121  ValueDisplayed: 10.0k  [0201L]  (hidden comment: CRCW020110K0FKED)
R123  ValueDisplayed: 10.0k  [0201L]  (hidden comment: CRCW020110K0FKED)
R181  ValueDisplayed: 10.0k  [0402L]  (hidden comment: CRCW040210K0FKED)
R182  ValueDisplayed: 0  [0201L]  (hidden comment: CRCW02010000Z0ED)
R183  ValueDisplayed: 22  [0201L]  (hidden comment: RC0201JR-0722RL)
R184  ValueDisplayed: 0  [0201L]  (hidden comment: CRCW02010000Z0ED)
R185  ValueDisplayed: 0  [0201L]  (hidden comment: CRCW02010000Z0ED)
R193  ValueDisplayed: 10.0k  [0402L]  (hidden comment: CRCW040210K0FKED)
R198  ValueDisplayed: 33.0  [0402L]  (hidden comment: RMCF0402FT33R0)
R199  ValueDisplayed: 0  [0402L]  (hidden comment: CRCW04020000Z0ED)
R200  ValueDisplayed: 0  [0402L]  (hidden comment: CRCW04020000Z0ED)
R208  ValueDisplayed: 0  [0201L]  (hidden comment: CRCW02010000Z0ED)
R209  ValueDisplayed: 0  [0201L]  (hidden comment: CRCW02010000Z0ED)
R210  ValueDisplayed: 0  [0201L]  (hidden comment: CRCW02010000Z0ED)
R211  ValueDisplayed: 0  [0201L]  (hidden comment: CRCW02010000Z0ED)
R212  ValueDisplayed: 22  [0201L]  (hidden comment: RC0201JR-0722RL)
R217  ValueDisplayed: 4.70k  [0201L]  (hidden comment: RC0201FR-074K7L)
R218  ValueDisplayed: 33.0  [0201L]  (hidden comment: RC0201FR-0733RL)
R219  ValueDisplayed: 4.70k  [0201L]  (hidden comment: RC0201FR-074K7L)
R227  ValueDisplayed: 22  [0201L]  (hidden comment: RC0201JR-0722RL)
R228  ValueDisplayed: 22  [0201L]  (hidden comment: RC0201JR-0722RL)
R229  ValueDisplayed: 22  [0201L]  (hidden comment: RC0201JR-0722RL)
R230  ValueDisplayed: 22  [0201L]  (hidden comment: RC0201JR-0722RL)
R231  ValueDisplayed: 22  [0201L]  (hidden comment: RC0201JR-0722RL)
R232  ValueDisplayed: 0  [0201L]  (hidden comment: CRCW02010000Z0ED)
R234  ValueDisplayed: 0  [0201L]  (hidden comment: CRCW02010000Z0ED)
R235  ValueDisplayed: 0  [0201L]  (hidden comment: CRCW02010000Z0ED)
R236  ValueDisplayed: 0  [0201L]  (hidden comment: CRCW02010000Z0ED)
R237  ValueDisplayed: 0  [0201L]  (hidden comment: CRCW02010000Z0ED)
R238  ValueDisplayed: 0  [0201L]  (hidden comment: CRCW02010000Z0ED)
TP1  TESTPOINT  [TP_25MIL-SMT]  (value not drawn)  (no BOM)
TP6  TESTPOINT  [TP_25MIL-SMT]  (value not drawn)  (no BOM)
TP29  TESTPOINT  [TP_25MIL-SMT]  (value not drawn)  (no BOM)
U2  AM2612AOFFHIZFGR  [ZFG0304A-MFG]  (parts A,B,C,D,E of 7)
U3  SN74LVC2G08DCUR  [DCU0008A_L]  (parts A,B,C of 3)
U4  SN74AHC1G09DCKR  [DCK0005A_L]  (parts A,B of 2)
U5  TS5A23159DGSR  [DGS0010A_L]
U6  SN74LVC1G125DSFR  [DSF0006A]  (parts A,B of 2)
U7  TCA6408ARGTR  [RGT0016A]
U8  LMK3C0105V33RERR  [RER0016A-MFG]
U29  SN74AHC1G09DCKR  [DCK0005A_L]  (parts A,B of 2)
U31  SN74LVC1G08DRLR  [DRL0005A]  (parts A,B of 2)
U47  SN74AHC1G08DRLR  [DRL0005A]  (parts A,B of 2)
U53  TXS0101DCKR  [DCK0006A_L]

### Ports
AM261_I2C0 (out, harness I2C), CLK_25M_PHY1 (out), CLK_25M_PHY2 (out), HPI (out, harness HPI), IE_UI_CTRL (out, harness IE_UI_CTRL), JTAG_UART (harness JTAG_UART), MII0 (out, harness MII), MII1 (out, harness MII), MMC0 (out, harness MMC), OSPI0_FLASH (out, harness OSPI), OSPI1_PSRAM (out, harness OSPI), PMIC_NRST (in), SOP_RESET (out, harness SOP_RESET), USB2_0 (harness USB2_0)

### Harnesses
MII: TXEN, MTn_CLK, RXD[3..0], RXDV, RXLINK, MDIO, MDC, TXD[3..0], ~{PHY_INT}, ~{PHY_RESET}, COL, CRS, RXER, MRn_CLK
OSPI: OSPI_CLK, OSPI_CSN0, OSPI_DQS, OSPI_ECC_FAIL, OSPI_D[7..0], OSPI_RSTN
SOP_RESET: SOP[3..0], PORZN_PB, WARMRSTN, PORZN
I2C: SCL, SDA
MMC: MMC_CLK, MMC_CD, MMC_CMD, MMC_D[3..0]
IE_UI_CTRL: I2C0_SDA, I2C0_SCL, I2C1_SDA, I2C1_SCL, UI_LED1_R, UI_LED1_G, UI_LED_SAFTY_ERR, USER_INT, UI_LED2_R, UI_LED2_G
JTAG_UART: TDI, TDO, TCK, TMS, UART_RX, UART_TX
HPI: SYNC[1..0], LATCH[1..0], INT[3..0], PRU0_GPIO[20..0], PRU1_GPIO[19..0], MDIO, MDC, SEL_HPI_SPI, SEL_HPI_FSI, HPI_RESET
USB2_0: USB_DM, USB_DP, USB_DRVVBUS, USB_MUX_SEL, USB0_VBUS_OC

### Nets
GND: C61.2 C62.1 C63.2 C64.2 C65.2 C66.2 C67.2 C68.1 C120.1 C121.1 C123.1 C175.2 C176.1 C178.2 C207.1 C208.1 C212.2 C213.1 C214.2 C215.1 C216.2 C217.1 R6.2 R14.2 R21.1 R181.2 R199.2 R200.2 U2.U13(ADC0_AIN1) U2.V9(ADC2_AIN5) U2.V12(ADC1_AIN1) U2.V14(ADC0_AIN3) U2.V16(ADC_CAL0) U2.W6(ADC2_AIN4) U2.W7(ADC2_AIN3) U2.W8(ADC2_AIN0) U2.W9(ADC1_AIN6) U2.W10(ADC1_AIN5) U2.W11(ADC1_AIN3) U2.W12(ADC1_AIN0) U2.W13(ADC0_AIN0) U2.W14(ADC0_AIN2) U2.W15(ADC0_AIN5) U2.Y5(ADC2_AIN6) U2.Y6(ADC2_AIN2) U2.Y7(ADC2_AIN1) U2.Y9(ADC_VREFLO_G1) U2.Y10(ADC1_AIN4) U2.Y11(ADC1_AIN2) U2.Y13(ADC_VREFLO_G0) U2.Y14(ADC0_AIN4) U2.Y15(ADC0_AIN6) U3.4(GND) U4.3(GND) U5.3(GND) U6.3(GND) U7.6(GND) U7.17(EP) U8.1(~{OE}) U8.17(DAP) U29.3(GND) U31.3(GND) U47.3(GND) U53.2(GND)
VDDA_AM261_1V8_LDO: C216.1 C217.2 U2.U15(DAC_VREF0)
VSYS_1V8: C207.2 L18.1 R9.2 R10.1 R193.1 U53.1(VCCA) U53.5(OE)
VSYS_3V3: C61.1 C62.2 C63.1 C120.2 C123.2 C175.1 C176.2 C178.1 C208.2 L17.1 R7.2 R8.2 R13.2 R15.1 R17.2 R22.1 R99.1 R100.1 R217.2 R219.2 U3.8(VCC) U4.5(VCC) U5.8(V+) U6.6(VCC) U7.15(VCCI) U29.5(VCC) U31.5(VCC) U47.5(VCC) U53.6(VCCB)
~{ETH0_PHY_INT}: U2.B4(GPIO83) ; port MII0.~{PHY_INT}
~{ETH1_PHY_INT}: U2.A10(GPIO22) ; port MII1.~{PHY_INT}
AM261_ETH0_RST: R6.1 U3.2(1B) U7.4(P2)
AM261_ETH1_RST: R14.1 U3.6(2B) U7.3(P1)
AM261_I2C0_SCL: R219.1 U2.A15(GPIO135) U7.12(SCL) U8.4(OTP_SEL1/SDA) ; off-sheet AM261_I2C0_SCL, port AM261_I2C0.SCL, port IE_UI_CTRL.I2C0_SCL  [project net AM261_I2C0.SCL]
AM261_I2C0_SDA: R17.1 U2.B15(GPIO134) U7.13(SDA) U8.3(OTP_SEL0/SCL) ; off-sheet AM261_I2C0_SDA, port AM261_I2C0.SDA, port IE_UI_CTRL.I2C0_SDA  [project net AM261_I2C0.SDA]
AM261_PORZN: R181.1 U2.V3(~{POR}) U3.1(1A) U3.5(2A) U31.4(Y) U47.1(A) ; port SOP_RESET.PORZN
AM261_SAFETY_ERR: U2.E3(~{SAFETY_ERROR}) ; port IE_UI_CTRL.UI_LED_SAFTY_ERR
AM261_SOP0: R16.1
AM261_SOP1: R120.1
AM261_SOP2: R121.1
AM261_SOP3: R123.1
AM261_TCK: U2.D4(TCK) ; port JTAG_UART.TCK
AM261_TDI: U2.C5(TDI) ; port JTAG_UART.TDI
AM261_TDO: R212.1 ; port JTAG_UART.TDO
AM261_TMS: U2.D6(TMS) ; port JTAG_UART.TMS
AM261_UART0_RXD: U2.A8(GPIO27) ; port JTAG_UART.UART_RX
AM261_UART0_TXD: R218.1 ; port JTAG_UART.UART_TX
AM261_USB0_D_N: U2.W1(GPIO140) ; port USB2_0.USB_DM
AM261_USB0_D_P: U2.V1(GPIO139) ; port USB2_0.USB_DP
AM261_USB0_DRVVBUS: U2.U2(GPIO121) ; port USB2_0.USB_DRVVBUS
AM261_USB0_MUX_SEL: U7.8(P5) ; port USB2_0.USB_MUX_SEL
AM261_USB0_VBUS_OC: U2.F2(GPIO55) ; port USB2_0.USB0_VBUS_OC
AM261_WARMRSTN: U2.G3(~{WARMRST}) U4.2(B) U29.2(B) U47.2(B) ; port SOP_RESET.WARMRSTN
CLK_25M: R19.2 ; port CLK_25M_PHY1
CLK_25M: R18.2 ; port CLK_25M_PHY2  [a separate net that carries the same name]
CLK_25M_MCU: R20.2 U2.Y3(XTAL_XI)
CPSW_MDIO0_MDC: U2.T18(GPIO42) U5.4(NO2)
CPSW_MDIO0_MDIO: U2.R17(GPIO41) U53.3(A)
CPSW_MDIO0_MDIO_3V3: U5.2(NO1) U53.4(B)
ETH0_RST: U3.7(1Y) ; port MII0.~{PHY_RESET}  [project net ~{PHY_RESET}]
ETH1_RST: U3.3(2Y) ; port MII1.~{PHY_RESET}  [project net ~{PHY_RESET}]
HPI_IRQ0: U2.T1(GPIO5)
HPI_IRQ1: U2.U1(GPIO6)
HPI_IRQ2: U2.B10(GPIO21)
HPI_IRQ3: U2.C19(GPIO120)
HPI_RESET: U47.4(Y) ; port HPI.HPI_RESET
MDIO/MDC_MUX_SEL: U5.1(IN1) U5.5(IN2) U7.5(P3)
MII_MDC: U5.6(COM2) ; port MII0.MDC, port MII1.MDC  [project net MDC]
MII_MDIO: U5.10(COM1) ; port MII0.MDIO, port MII1.MDIO  [project net MDIO]
MMC0_CD: U2.A7(GPIO84) ; port MMC0.MMC_CD
MMC0_CLK: R183.2 ; port MMC0.MMC_CLK
MMC0_CMD: R227.2 ; port MMC0.MMC_CMD
MMC0_D0: R228.2
MMC0_D1: R229.2
MMC0_D2: R230.2
MMC0_D3: R231.2
OSPI0_CLK: R184.1 ; port OSPI0_FLASH.OSPI_CLK
OSPI0_CSN0: U2.L2(GPIO62) ; port OSPI0_FLASH.OSPI_CSN0
OSPI0_D0: U2.M3(GPIO2)
OSPI0_D1: U2.M2(GPIO70)
OSPI0_D2: U2.P1(GPIO7)
OSPI0_D3: U2.L1(GPIO69)
OSPI0_D4: U2.R4(GPIO76)
OSPI0_D5: U2.K1(GPIO67)
OSPI0_D6: U2.P2(GPIO8)
OSPI0_D7: U2.L4(GPIO68)
OSPI0_DQS: R182.1 ; port OSPI0_FLASH.OSPI_DQS
OSPI0_ECC_FAIL: U2.J3(GPIO65) ; port OSPI0_FLASH.OSPI_ECC_FAIL
OSPI0_RESET_OUT: U2.K4(GPIO61) U6.2(A)
OSPI0_RSTN: R193.2 U29.4(Y) ; port OSPI0_FLASH.OSPI_RSTN
OSPI1_CLK: R185.1 ; port OSPI1_PSRAM.OSPI_CLK
OSPI1_CSN0: U2.V20(GPIO38) ; port OSPI1_PSRAM.OSPI_CSN0
OSPI1_D0: U2.V19(GPIO30)
OSPI1_D1: U2.Y18(GPIO31)
OSPI1_D2: U2.W18(GPIO32)
OSPI1_D3: U2.Y19(GPIO33)
OSPI1_D4: U2.W19(GPIO34)
OSPI1_D5: U2.U20(GPIO35)
OSPI1_D6: U2.T20(GPIO36)
OSPI1_D7: U2.V18(GPIO37)
OSPI1_DQS: R232.1 ; port OSPI1_PSRAM.OSPI_DQS
OSPI1_RESET_OUT: R9.1 U2.K2(GPIO66) U4.1(A)
OSPI1_RSTN: R10.2 U4.4(Y) ; port OSPI1_PSRAM.OSPI_RSTN
OSPI_BUF_EN: R7.1 U2.F1(GPIO56) U6.1(~{OE})
PMIC_NRST: U31.1(A) ; port PMIC_NRST
PORZ_PB: U31.2(B) ; port SOP_RESET.PORZN_PB
PR0_IEP0_EDC_LATCH_IN0: U2.A14(GPIO137)
PR0_IEP0_EDC_LATCH_IN1: U2.B19(GPIO122)
PR0_IEP0_EDC_SYNC_OUT0: U2.C18(GPIO119)
PR0_IEP0_EDC_SYNC_OUT1: U2.T19(GPIO40)
PR0_MII0_COL: U2.J19(GPIO88) ; port MII0.COL  [project net COL]
PR0_MII0_CRS: U2.J20(GPIO89) ; port MII0.CRS  [project net CRS]
PR0_MII0_RXD0: U2.N17(GPIO93)
PR0_MII0_RXD1: U2.N19(GPIO94)
PR0_MII0_RXD2: U2.M18(GPIO95)
PR0_MII0_RXD3: U2.M20(GPIO96)
PR0_MII0_RXDV: U2.L20(GPIO92) ; port MII0.RXDV
PR0_MII0_RXER: U2.K19(GPIO87) ; port MII0.RXER
PR0_MII0_RXLINK: U2.J18(GPIO90) ; port MII0.RXLINK  [project net ETH0_LED_LINK]
PR0_MII0_TXD0: R234.2
PR0_MII0_TXD1: R235.2
PR0_MII0_TXD2: R236.2
PR0_MII0_TXD3: R237.2
PR0_MII0_TXEN: U2.E18(GPIO114) ; port MII0.TXEN
PR0_MII1_COL: U2.E20(GPIO104) ; port MII1.COL  [project net COL]
PR0_MII1_CRS: U2.E19(GPIO105) ; port MII1.CRS  [project net CRS]
PR0_MII1_RXD0: U2.H20(GPIO109)
PR0_MII1_RXD1: U2.H19(GPIO110)
PR0_MII1_RXD2: U2.H17(GPIO111)
PR0_MII1_RXD3: U2.G20(GPIO112)
PR0_MII1_RXDV: U2.G19(GPIO108) ; port MII1.RXDV
PR0_MII1_RXER: U2.F20(GPIO103) ; port MII1.RXER
PR0_MII1_RXLINK: U2.G18(GPIO106) ; port MII1.RXLINK  [project net ETH1_LED_LINK]
PR0_MII1_TXD0: R208.2
PR0_MII1_TXD1: R209.2
PR0_MII1_TXD2: R210.2
PR0_MII1_TXD3: R211.2
PR0_MII1_TXEN: U2.P18(GPIO98) ; port MII1.TXEN
PR0_MII_MDC: U2.R20(GPIO86) U5.7(NC2)
PR0_MII_MDIO: U2.R19(GPIO85) U5.9(NC1)
PR0_MII_MR0_CLK: U2.N20(GPIO91) ; port MII0.MRn_CLK  [project net MRn_CLK]
PR0_MII_MR1_CLK: U2.F19(GPIO107) ; port MII1.MRn_CLK  [project net MRn_CLK]
PR0_MII_MT0_CLK: U2.B20(GPIO113) ; port MII0.MTn_CLK  [project net MTn_CLK]
PR0_MII_MT1_CLK: U2.M19(GPIO97) ; port MII1.MTn_CLK  [project net MTn_CLK]
PR1_MDIO0_MDC: U2.A18(GPIO126) ; port HPI.MDC
PR1_MDIO0_MDIO: U2.A17(GPIO127) ; port HPI.MDIO
PR1_PRU0_GPIO0: R123.2 U2.B12(GPIO13)
PR1_PRU0_GPIO1: U2.C12(GPIO14)
PR1_PRU0_GPIO2: U2.B13(GPIO11)
PR1_PRU0_GPIO3: U2.B1(GPIO47)
PR1_PRU0_GPIO4: U2.A3(GPIO46)
PR1_PRU0_GPIO5: U2.B3(GPIO43)
PR1_PRU0_GPIO6: U2.A2(GPIO45)
PR1_PRU0_GPIO7: U2.D8(GPIO26)
PR1_PRU0_GPIO8: U2.C3(GPIO44)
PR1_PRU0_GPIO9: R121.2 U2.A13(GPIO12)
PR1_PRU0_GPIO10: U2.A19(GPIO124)
PR1_PRU0_GPIO11: U2.C2(GPIO50)
PR1_PRU0_GPIO12: U2.D2(GPIO51)
PR1_PRU0_GPIO13: U2.D1(GPIO52)
PR1_PRU0_GPIO14: U2.E2(GPIO53)
PR1_PRU0_GPIO15: U2.C1(GPIO49)
PR1_PRU0_GPIO16: U2.B2(GPIO48)
PR1_PRU0_GPIO17: R217.1 U2.B9(GPIO23) ; port IE_UI_CTRL.I2C1_SCL
PR1_PRU0_GPIO18: R13.1 U2.A9(GPIO24) ; port IE_UI_CTRL.I2C1_SDA
PR1_PRU0_GPIO19: U2.B16(GPIO131)
PR1_PRU0_GPIO20: U2.C14(GPIO132)
PR1_PRU1_GPIO0: U2.W16(GPIO71)
PR1_PRU1_GPIO1: U2.Y16(GPIO72)
PR1_PRU1_GPIO2: U2.W17(GPIO73)
PR1_PRU1_GPIO3: U2.A12(GPIO16)
PR1_PRU1_GPIO4: U2.D11(GPIO15)
PR1_PRU1_GPIO5: U2.E1(GPIO54)
PR1_PRU1_GPIO6: U2.A11(GPIO19)
PR1_PRU1_GPIO7: U2.D15(GPIO133)
PR1_PRU1_GPIO8: U2.B11(GPIO20)
PR1_PRU1_GPIO9: U2.Y17(GPIO74)
PR1_PRU1_GPIO10: U2.C16(GPIO123)
PR1_PRU1_GPIO11: R16.2 U2.R2(GPIO3)
PR1_PRU1_GPIO12: R120.2 U2.R1(GPIO4)
PR1_PRU1_GPIO13: U2.B17(GPIO125)
PR1_PRU1_GPIO14: U2.B18(GPIO128)
PR1_PRU1_GPIO15: U2.C9(GPIO18)
PR1_PRU1_GPIO16: U2.D10(GPIO17)
PR1_PRU1_GPIO17: R238.2
PR1_PRU1_GPIO18: U2.A16(GPIO130)
PR1_PRU1_GPIO19: U2.C7(GPIO25)
SEL_HPI_FSI: U7.9(P6) ; port HPI.SEL_HPI_FSI
SEL_HPI_SPI: U7.10(P7) ; port HPI.SEL_HPI_SPI
UI_LED1_G: U2.T2(GPIO1) ; port IE_UI_CTRL.UI_LED1_G
UI_LED1_R: U2.U4(GPIO0) ; port IE_UI_CTRL.UI_LED1_R
UI_LED2_G: U2.J1(GPIO64) ; port IE_UI_CTRL.UI_LED2_G
UI_LED2_R: U2.J2(GPIO63) ; port IE_UI_CTRL.UI_LED2_R
USER_INT: U2.B14(GPIO136) ; port IE_UI_CTRL.USER_INT
NetC64_1: C64.1 C65.1 C66.1 C67.1 L17.2 U8.5(VDD) U8.10(VDDO_0) U8.14(VDD) U8.16(VDD)
NetC68_2: C68.2 L18.2 U8.13(VDDO_1)
NetC121_2: C121.2 U7.14(VCCP)
NetC212_1: C212.1 C213.2 U2.Y8(ADC_VREFHI_G1)
NetC214_1: C214.1 C215.2 U2.Y12(ADC_VREFHI_G0)
NetR8_1: R8.1 U6.4(Y) U29.1(A)
NetR15_2: R15.2 U7.16(ADDR)
NetR18_1: R18.1 U8.8(OUTA)
NetR19_1: R19.1 U8.7(OUTB)
NetR20_1: R20.1 U8.12(OUTC)
NetR21_2: R21.2 U8.15(REF_CTRL(OUTE))
NetR22_2: R22.2 U8.2(I2C_ADDR)
NetR99_2: R99.2 U7.11(~{INT})
NetR100_2: R100.2 U7.1(~{RESET})
NetR182_2: R182.2 U2.N2(GPIO9)
NetR183_1: R183.1 U2.B7(GPIO77)
NetR184_2: R184.2 U2.N1(GPIO10)
NetR185_2: R185.2 U2.W20(GPIO29)
NetR198_1: R198.1 U8.11(OUTD)
NetR198_2: R198.2 TP1.1
NetR199_1: R199.1 U8.6(NC)
NetR200_1: R200.1 U8.9(NC)
NetR208_1: R208.1 U2.P20(GPIO99)
NetR209_1: R209.1 U2.P19(GPIO100)
NetR210_1: R210.1 U2.K20(GPIO101)
NetR211_1: R211.1 U2.L19(GPIO102)
NetR212_2: R212.2 U2.E5(TDO)
NetR218_2: R218.2 U2.B8(GPIO28)
NetR227_1: R227.1 U2.A6(GPIO78)
NetR228_1: R228.1 U2.B6(GPIO79)
NetR229_1: R229.1 U2.A5(GPIO80)
NetR230_1: R230.1 U2.B5(GPIO81)
NetR231_1: R231.1 U2.A4(GPIO82)
NetR232_2: R232.2 U2.U19(GPIO39)
NetR234_1: R234.1 U2.F17(GPIO115)
NetR235_1: R235.1 U2.D20(GPIO116)
NetR236_1: R236.1 U2.C20(GPIO117)
NetR237_1: R237.1 U2.D19(GPIO118)
NetR238_1: R238.1 U2.D17(GPIO129)
NetTP6_1: TP6.1 U7.2(P0)
NetTP29_1: TP29.1 U7.7(P4)

Not connected (* = marked no-connect by the designer): U2 G1(GPIO58) G2(GPIO57) H1(GPIO60) H2(GPIO59) M1(GPIO138) T3(GPIO75) U17(NC)* W3(TEMPCAL)* W4(DAC_OUT)* W5(ATESTV1)* Y2(XTAL_XO)*; U6 5(NC)*

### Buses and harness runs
bus AM261_SOP[3..0]
bus HPI_IRQ[3..0]
bus MMC0_D[3..0]
bus OSPI0_D[7..0]
bus OSPI1_D[7..0]
bus PR0_IEP0_EDC_LATCH_IN[1..0]
bus PR0_IEP0_EDC_SYNC_OUT[1..0]
bus PR0_MII0_RXD[3..0]
bus PR0_MII0_TXD[3..0]
bus PR0_MII1_RXD[3..0]
bus PR0_MII1_TXD[3..0]
bus PR1_PRU0_GPIO[20..0]
bus PR1_PRU1_GPIO[19..0]

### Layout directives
net class MII0_TX: PR0_MII0_TXD[3..0], PR0_MII0_TXEN, PR0_MII_MT0_CLK
net class MII0_RX: PR0_MII0_RXD[3..0], PR0_MII0_RXDV, PR0_MII0_RXER, PR0_MII_MR0_CLK
net class MII1_RX: PR0_MII1_RXD[3..0], PR0_MII1_RXDV, PR0_MII1_RXER, PR0_MII_MR1_CLK
net class MII1_TX: PR0_MII1_TXD[3..0], PR0_MII1_TXEN, PR0_MII_MT1_CLK
net class OSPI_FLASH: OSPI0_CLK, OSPI0_CSN0, OSPI0_D[7..0], OSPI0_DQS
net class OSPI_PSRAM: OSPI1_CLK, OSPI1_CSN0, OSPI1_D[7..0], OSPI1_DQS
differential pair: AM261_USB0_D_N, AM261_USB0_D_P

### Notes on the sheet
- Industrial Ethernet
- Length match the following busses
  MII_RX, MII_TX, OSPI Flash, OSPI PSRAM, SD Card
- 1.8V IOs: GPIO 7-10, 29-41, 57-70, 76, 138
- (near R217) I2C pull-up
- (near U3) OSPI FLASH
- 1.8V IO: GPIO40/GPIO41
- OSPI PSRAM
- MDIO ICSS0/CPSW MUX
- (near U7) I2C IO Expanders
- Text
- I2C address: 0x21
- (near R16) AM261x SOP[3:0]
- Place as close to MCU as possible: R16, R120, R121, R123
- Clock Buffer with BAW oscillator
- (near U31) POR Generation
- PHY: 3.3V level
- AM261x: 1.8V level
- (near U2) AM261 JTAG
- (near U8) I2C address: 0x69 / 0xD2

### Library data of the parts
C61 C62 C120 C121 C123 C175 C176 C178 C207 C208 = CMP-0006221-2: CAP, CERM, 0.1 uF, 10 V, +/- 20%, X5R, 0402; Manufacturer: Wurth Elektronik; TaMin_C: -55°C; Polarized: N; SizeAreaWB_mm2: 3; Value1: Unknown; U/M: EA; Value: 0.1uF; TaMax_C: 85°C; SizeZ_mm: 0.6; SizeX_mm: 1; SizeY_mm: 0.5; Cap_Case: 0402; Cap_F: 100nF; AEC Category: Q200
C63-C68 = CMP-0006228-2: CAP, CERM, 0.1 uF, 16 V, +/- 10%, X7R, 0402; Manufacturer: Wurth Elektronik; TaMin_C: -55°C; Polarized: N; SizeAreaWB_mm2: 3; Value1: Unknown; U/M: EA; Value: 0.1uF; TaMax_C: 125°C; SizeZ_mm: 0.6; SizeX_mm: 1; SizeY_mm: 0.5; Cap_Case: 0402; Cap_F: 100nF; AEC Category: Q200
C212 C214 C216 = CMP-0006265-2: as C14 on sheet TIDA-010973_SOM_PMIC
C213 C215 C217 = CMP-0049180-1: as C1 on sheet TIDA-010973_SOM_PMIC
L17 L18 = CMP-0003175-2: Ferrite Bead, 22 ohm @ 100 MHz, 1 A, 0603; Manufacturer: Wurth Elektronik; Ztyp@1GHz_Ohm: 35.365; ZTyp@100MHz_Ohm: 22; SizeAreaWB_mm2: 4.68; DCR_ohm: 0.05; Value1: 0.05 ohm; Value: 22 ohm; Imax_A: 1A; SizeZ_mm: 1; SizeX_mm: 1.6; SizeY_mm: 0.8; SizeArea_mm2: 1.28
R6-R10 R14 R15 R21 R99 R100 R181 R193 = CMP-0025958-3: as R1 on sheet TIDA-010973_SOM_PMIC
R13 R17 R217 R219 = CMP-0027743-1: RES, 4.70 k, 1%, 0.05 W, 0201; Manufacturer: Yageo America; Power_W: 50mW; TempCo: 200 ppm/C; Value_Code: 4k70; U/M: EA; Value: 4.70k; Res_ohm: 4.7k; SizeX_mm: 0.6; SizeY_mm: 0.3; SizeZ_mm: 0.26; Value2: 0.05W; SizeArea_mm2: 0.18; AEC Qualified: N; VDC_V: 25V; AEC Category: Q200
R16 R120 R121 R123 = CMP-0027262-3: RES, 10.0 k, 1%, 0.05 W, 0201; Manufacturer: Vishay-Dale; Power_W: 50mW; TempCo: 100 ppm/C; Value_Code: 10k0; Value: 10.0k; EIA_Code: E96; Res_ohm: 10k; SizeX_mm: 0.6; SizeY_mm: 0.3; SizeZ_mm: 0.26; Value2: 0.05W; SizeArea_mm2: 0.18; AEC Qualified: N; VDC_V: 30V; AEC Category: Q200
R18-R20 R198 = CMP-0026759-1: RES, 33.0, 1%, 0.063 W, AEC-Q200 Grade 0, 0402; Manufacturer: Stackpole Electronics Inc; Power_W: 63mW; TempCo: 100 ppm/C; Value_Code: 33R0; U/M: EA; Value: 33.0; Res_ohm: 33; SizeX_mm: 1; SizeY_mm: 0.5; SizeZ_mm: 0.6; Value2: 0.063W; AEC Qualified: Y; VDC_V: 50V; AEC Grade: 0; AEC Category: Q200
R22 R199 R200 = CMP-0026822-3: RES, 0, 5%, 0.063 W, AEC-Q200 Grade 0, 0402; Manufacturer: Vishay-Dale; Power_W: 63mW; TempCo: 200 ppm/C; Value_Code: 0000; Value: 0; EIA_Code: E24; SizeX_mm: 1; SizeY_mm: 0.5; SizeZ_mm: 0.6; Value2: 0.063W; AEC Qualified: Y; VDC_V: 50V; AEC Category: Q200
R182 R184 R185 R208-R211 R232 R234-R238 = CMP-0027008-4: RES, 0, 5%, 0.05 W, 0201; Manufacturer: Vishay-Dale; Power_W: 50mW; TempCo: ppm/C; Value_Code: 0000; Value: 0; EIA_Code: E24; SizeX_mm: 0.6; SizeY_mm: 0.3; SizeZ_mm: 0.26; Value2: 0.05W; SizeArea_mm2: 0.18; AEC Qualified: N; AEC Category: Q200
R183 R212 R227-R231 = CMP-0027074-3: RES, 22, 5%, 0.05 W, 0201; Manufacturer: Yageo America; Power_W: 50mW; TempCo: 200 ppm/C; Value_Code: 22R0; U/M: EA; Value: 22; EIA_Code: E24; SizeX_mm: 0.6; SizeY_mm: 0.3; SizeZ_mm: 0.26; Value2: 0.05W; SizeArea_mm2: 0.18; AEC Qualified: N; VDC_V: 25V; AEC Category: Q200
R218 = CMP-0027615-1: RES, 33.0, 1%, 0.05 W, 0201; Manufacturer: Yageo America; Power_W: 50mW; TempCo: 200 ppm/C; Value_Code: 33R0; U/M: EA; Value: 33.0; Res_ohm: 33; SizeX_mm: 0.6; SizeY_mm: 0.3; SizeZ_mm: 0.26; Value2: 0.05W; SizeArea_mm2: 0.18; AEC Qualified: N; VDC_V: 25V; AEC Category: Q200
TP1 TP6 TP29 = CMP-0078143-4: TEST POINT.  No entry in BOM.
U2 = CMP-0126016-1: as U2 on sheet TIDA-010973_SOM_PMIC
U3 = CMP-0051796-2: Dual 2-Input Positive-AND Gate, DCU0008A (VSSOP-8); Manufacturer: Texas Instruments; Logic: True; Output Drive (IOL/IOH)(Max)(mA): 32/-32; F @ Nom Voltage(Max)(Mhz): 150; Technology Family: LVC; Rating: Catalog; tpd @ Nom Voltage(Max)(ns): 9.8,5.8,5.3,4.8; Voltage(Nom)(V): 1.8,2.5,3.3,5; Schmitt Trigger: No; Input Type: CMOS/TTL; Bits(#): 2; Gate Type: AND; VCC(Max)(V): 5.5; VCC(Min)(V): 1.65; ICC @ Nom Voltage(Max)(mA): 0.01; Output Type: CMOS; AEC Category: Q200; AEC Qualified: N; CompType: IC; SizeAreaWB_mm2: 12.6; SizeArea_mm2: 6.4; SizeX_mm: 3.2; SizeY_mm: 2.0; SizeZ_mm: 0.9
U4 U29 = CMP-0051263-2: Single 2-Input Positive–AND Gate with Open Drain Output, DCK0005A, LARGE T&R; Manufacturer: Texas Instruments; Output Type: CMOS; Rating: Catalog; Voltage(Nom)(V): 3.3,5; Bits(#): 1; Logic: True; tpd @ Nom Voltage(Max)(ns): 11,7.5; Schmitt Trigger: No; ICC @ Nom Voltage(Max)(mA): 0.01; Output Drive (IOL/IOH)(Max)(mA): 50/-50; Gate Type: AND; VCC(Max)(V): 5.5; F @ Nom Voltage(Max)(Mhz): 75; VCC(Min)(V): 2; Technology Family: AHC; AEC Category: Q200; AEC Qualified: N; CompType: IC; SizeAreaWB_mm2: 9.3; SizeArea_mm2: 4.2; SizeX_mm: 2.1; SizeY_mm: 2.0; SizeZ_mm: 1.1
U5 = CMP-0067419-2: 2-Channel, 2:1 Analog Switch with Low On-State Resistance (1ohm) and Powered Off Protection, DGS0010A (VSSOP-10); Alternate PartNumber: TS5A23159DGST; Alternate Manufacturer: Texas Instruments; Green_Lifecycle: Active; SizeAreaWB_mm2: 23.6; Green_REACh: Passed; SizeZ_mm: 1.1; SizeX_mm: 4.9; SizeY_mm: 3.0; SizeArea_mm2: 14.7; CompType: IC; AEC Category: Q200; AEC Qualified: N; Rating: Catalog
U6 = CMP-0051428-5: Single Bus Buffer Gate With 3-State Outputs, DSF0006A, LARGE T&R; Manufacturer: Texas Instruments; Output Type: CMOS; Bits(#): 1; Input Type: CMOS/TTL; Technology Family: LVC; Schmitt Trigger: No; 3-State Output: Yes; VCC(Max)(V): 5.5; Sub-Family: Non-Inverting Buffer/Driver; Rating: Catalog; Output Drive (IOL/IOH)(Max)(mA): 32/-32; ICC @ Nom Voltage(Max)(mA): 0.01; VCC(Min)(V): 1.65; F @ Nom Voltage(Max)(Mhz): 150; Logic: True; Voltage(Nom)(V): 1.8,2.5,3.3,5; tpd @ Nom Voltage(Max)(ns): 9,5.5,4.5,4; AEC Category: Q200; AEC Qualified: N; CompType: IC
U7 = CMP-0043157-2: Low-Voltage 8-Bit I2C and SMBus I/O Expander, 1.65 to 5.5 V, -40 to 85 degC, 16-pin QFN (RGT), Green (RoHS & no Sb/Br); Manufacturer: Texas Instruments; # of I/Os: 8; I2C Address: 0100 00x; Reset Input: Yes; Max Frequency(kHz): 400; VCC(Max)(V): 5.5; SubFamily: I2C IO Expander; VCC(Min)(V): 1.65
U8 = CMP-0126121-1: 5 output reference-less clock generator with bulk acoustic wave (BAW) 16-TQFN -40 to 85; Manufacturer: Texas Instruments; SizeZ_mm: 1.2mm; AEC Qualified: No; Interface: I2C; Max Frequency: 200MHz; Max Supply Voltage: 3.465V; Min Supply Voltage: 1.71V; Number Of Outputs: 5; Standoff Height: 0mm; TaMax_C: +85°C; TaMin_C: -40°C; TJmax_C: +105°C
U31 = CMP-0051585-3: Single 2-Input Positive-AND Gate, DRL0005A, LARGE T&R; Manufacturer: Texas Instruments; Rating: Catalog; Technology Family: LVC; 3-State Output: No; ICC @ Nom Voltage(Max)(mA): 0.01; VCC(Min)(V): 1.65; Logic: True; tpd @ Nom Voltage(Max)(ns): 4.5,6,4,5; Gate Type: AND; Output Drive (IOL/IOH)(Max)(mA): 32/-32; Bits(#): 1; Input Type: CMOS/TTL; VCC(Max)(V): 5.5; Output Type: CMOS; Voltage(Nom)(V): 1.8,2.5,3.3,5; F @ Nom Voltage(Max)(Mhz): 150; AEC Category: Q200; AEC Qualified: N; CompType: IC; SizeX_mm: 1.6; SizeZ_mm: 0.6
U47 = CMP-0051558-2: Single 2-Input Positive-AND Gate, DRL0005A, LARGE T&R; Manufacturer: Texas Instruments; tpd @ Nom Voltage(Max)(ns): 12.3,7.9; Bits(#): 1; Voltage(Nom)(V): 3.3,5; Output Type: CMOS; VCC(Min)(V): 2; VCC(Max)(V): 5.5; ICC @ Nom Voltage(Max)(mA): 0.01; Rating: Catalog; Gate Type: AND; Technology Family: AHC; Schmitt Trigger: No; Logic: True; F @ Nom Voltage(Max)(Mhz): 75; Output Drive (IOL/IOH)(Max)(mA): 50/-50; AEC Category: Q200; AEC Qualified: N; CompType: IC; SizeArea_mm2: 2.56; SizeX_mm: 1.6; SizeZ_mm: 0.6
U53 = CMP-0074352-3: 1-Bit Bidirectional Voltage-Level Shifter for Open-Drain and Push-Pull Application, DCK0006A (SOT-SC70-6); Alternate PartNumber: TXS0101DCKT; Manufacturer: Texas Instruments; SizeZ_mm: 1.1; SizeX_mm: 2.1; SizeY_mm: 2.0; SizeArea_mm2: 4.2; CompType: IC; SizeAreaWB_mm2: 9.3; AEC Category: Q200; AEC Qualified: N; Rating: Catalog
